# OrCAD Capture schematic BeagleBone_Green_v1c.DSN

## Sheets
1 P01_Title Page: title: BeagleBone Green Cover Page; rev: v1
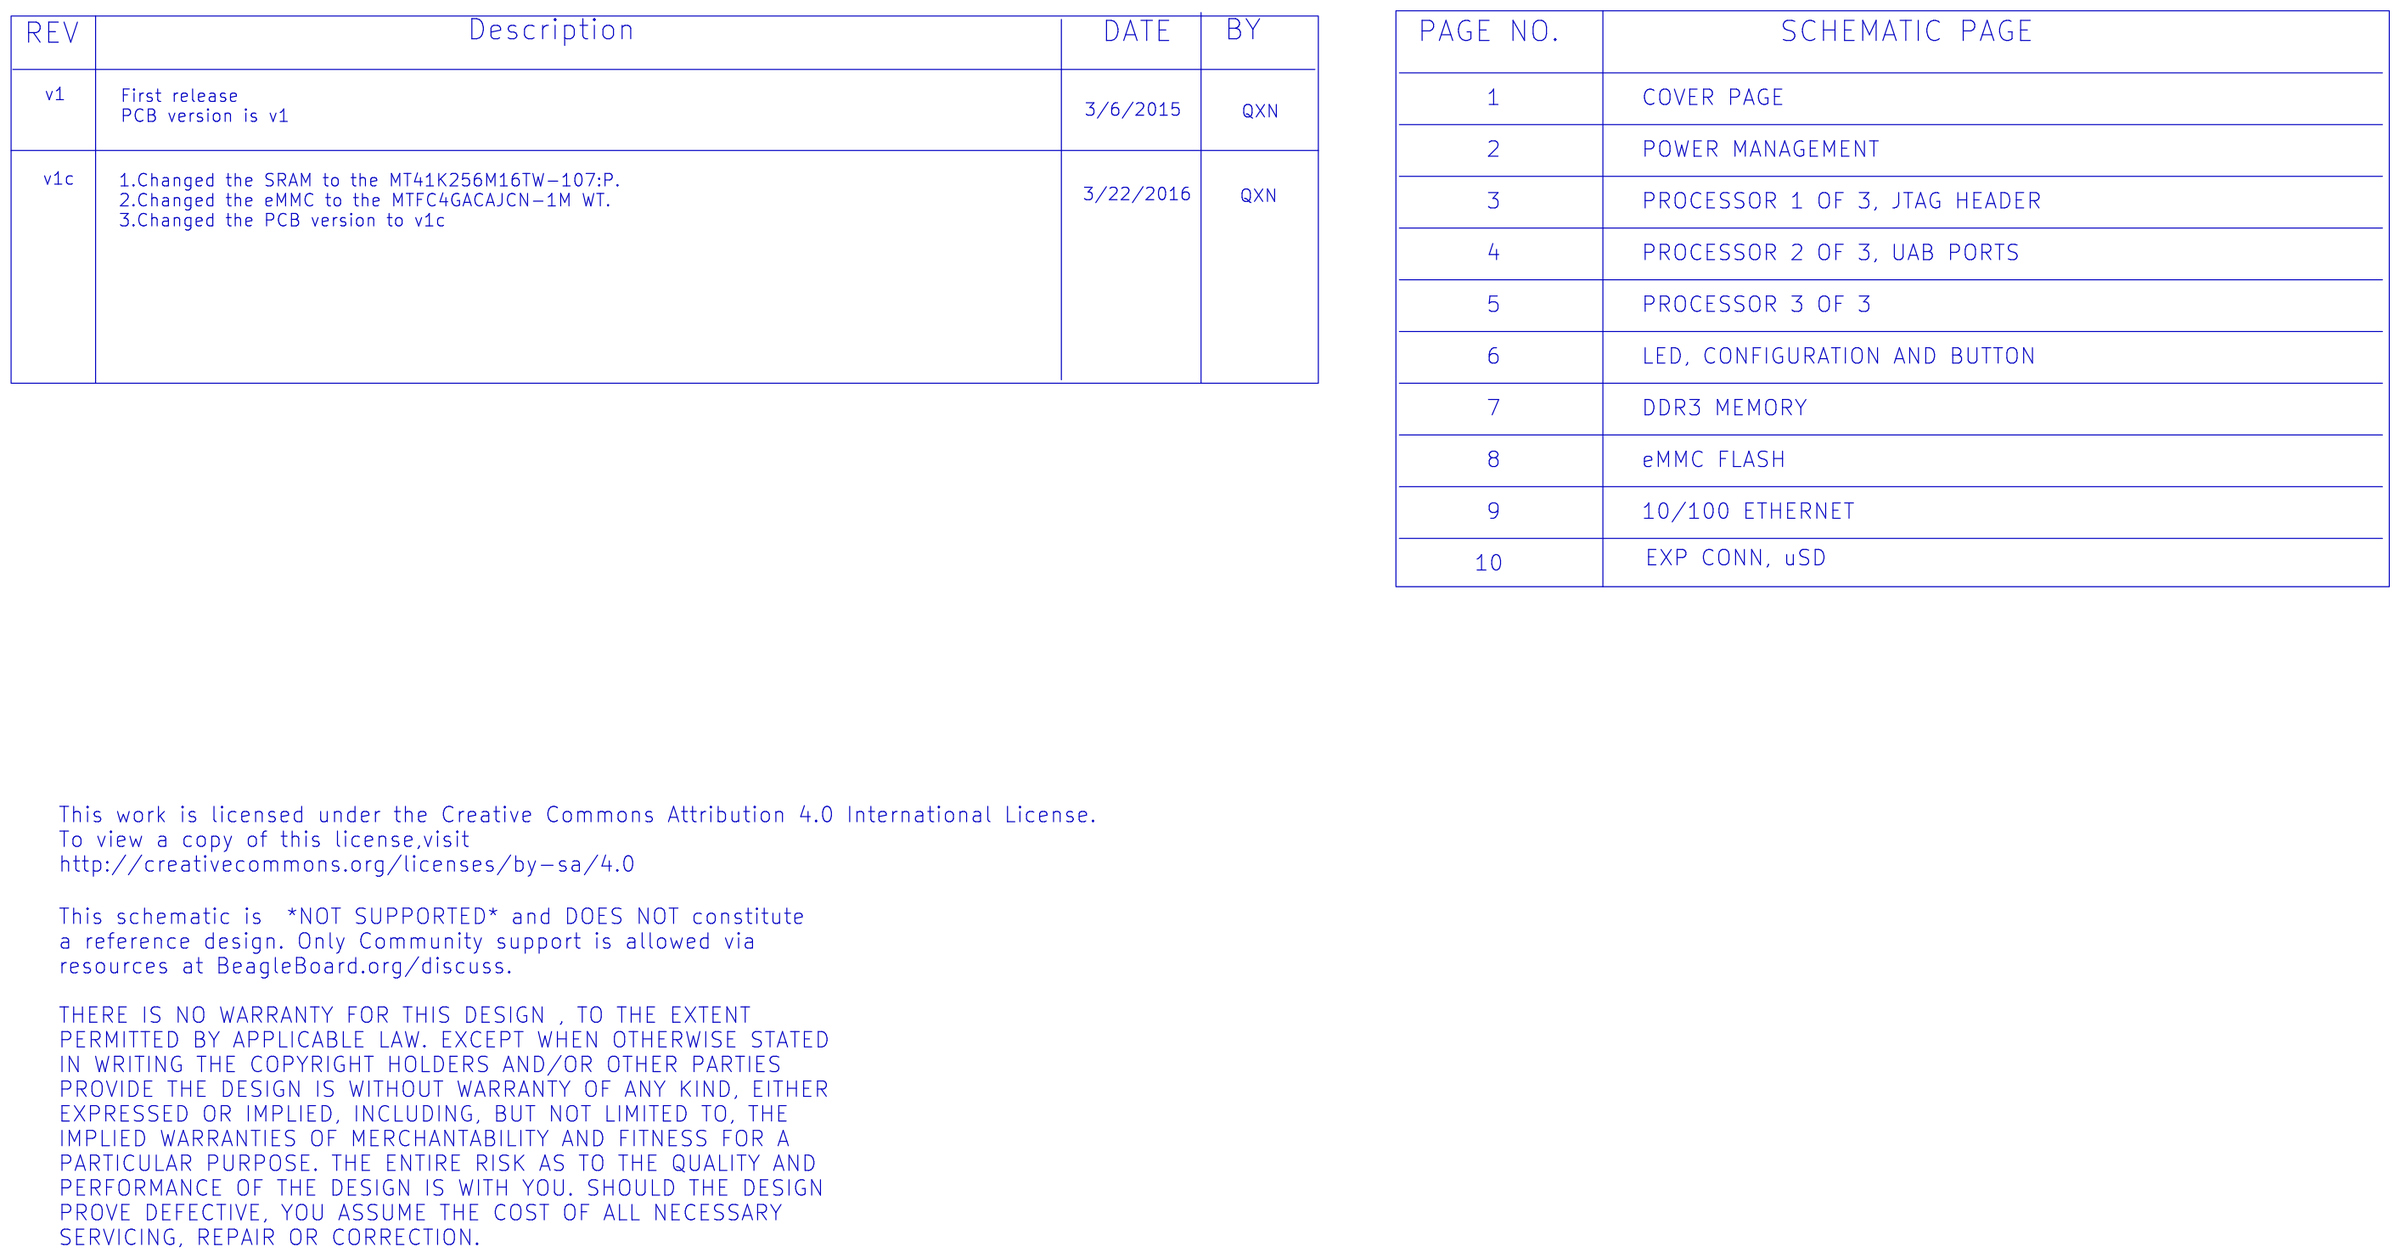
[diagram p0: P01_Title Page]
2 P02_Power Management: size B; title: BeagleBone Green Power Management
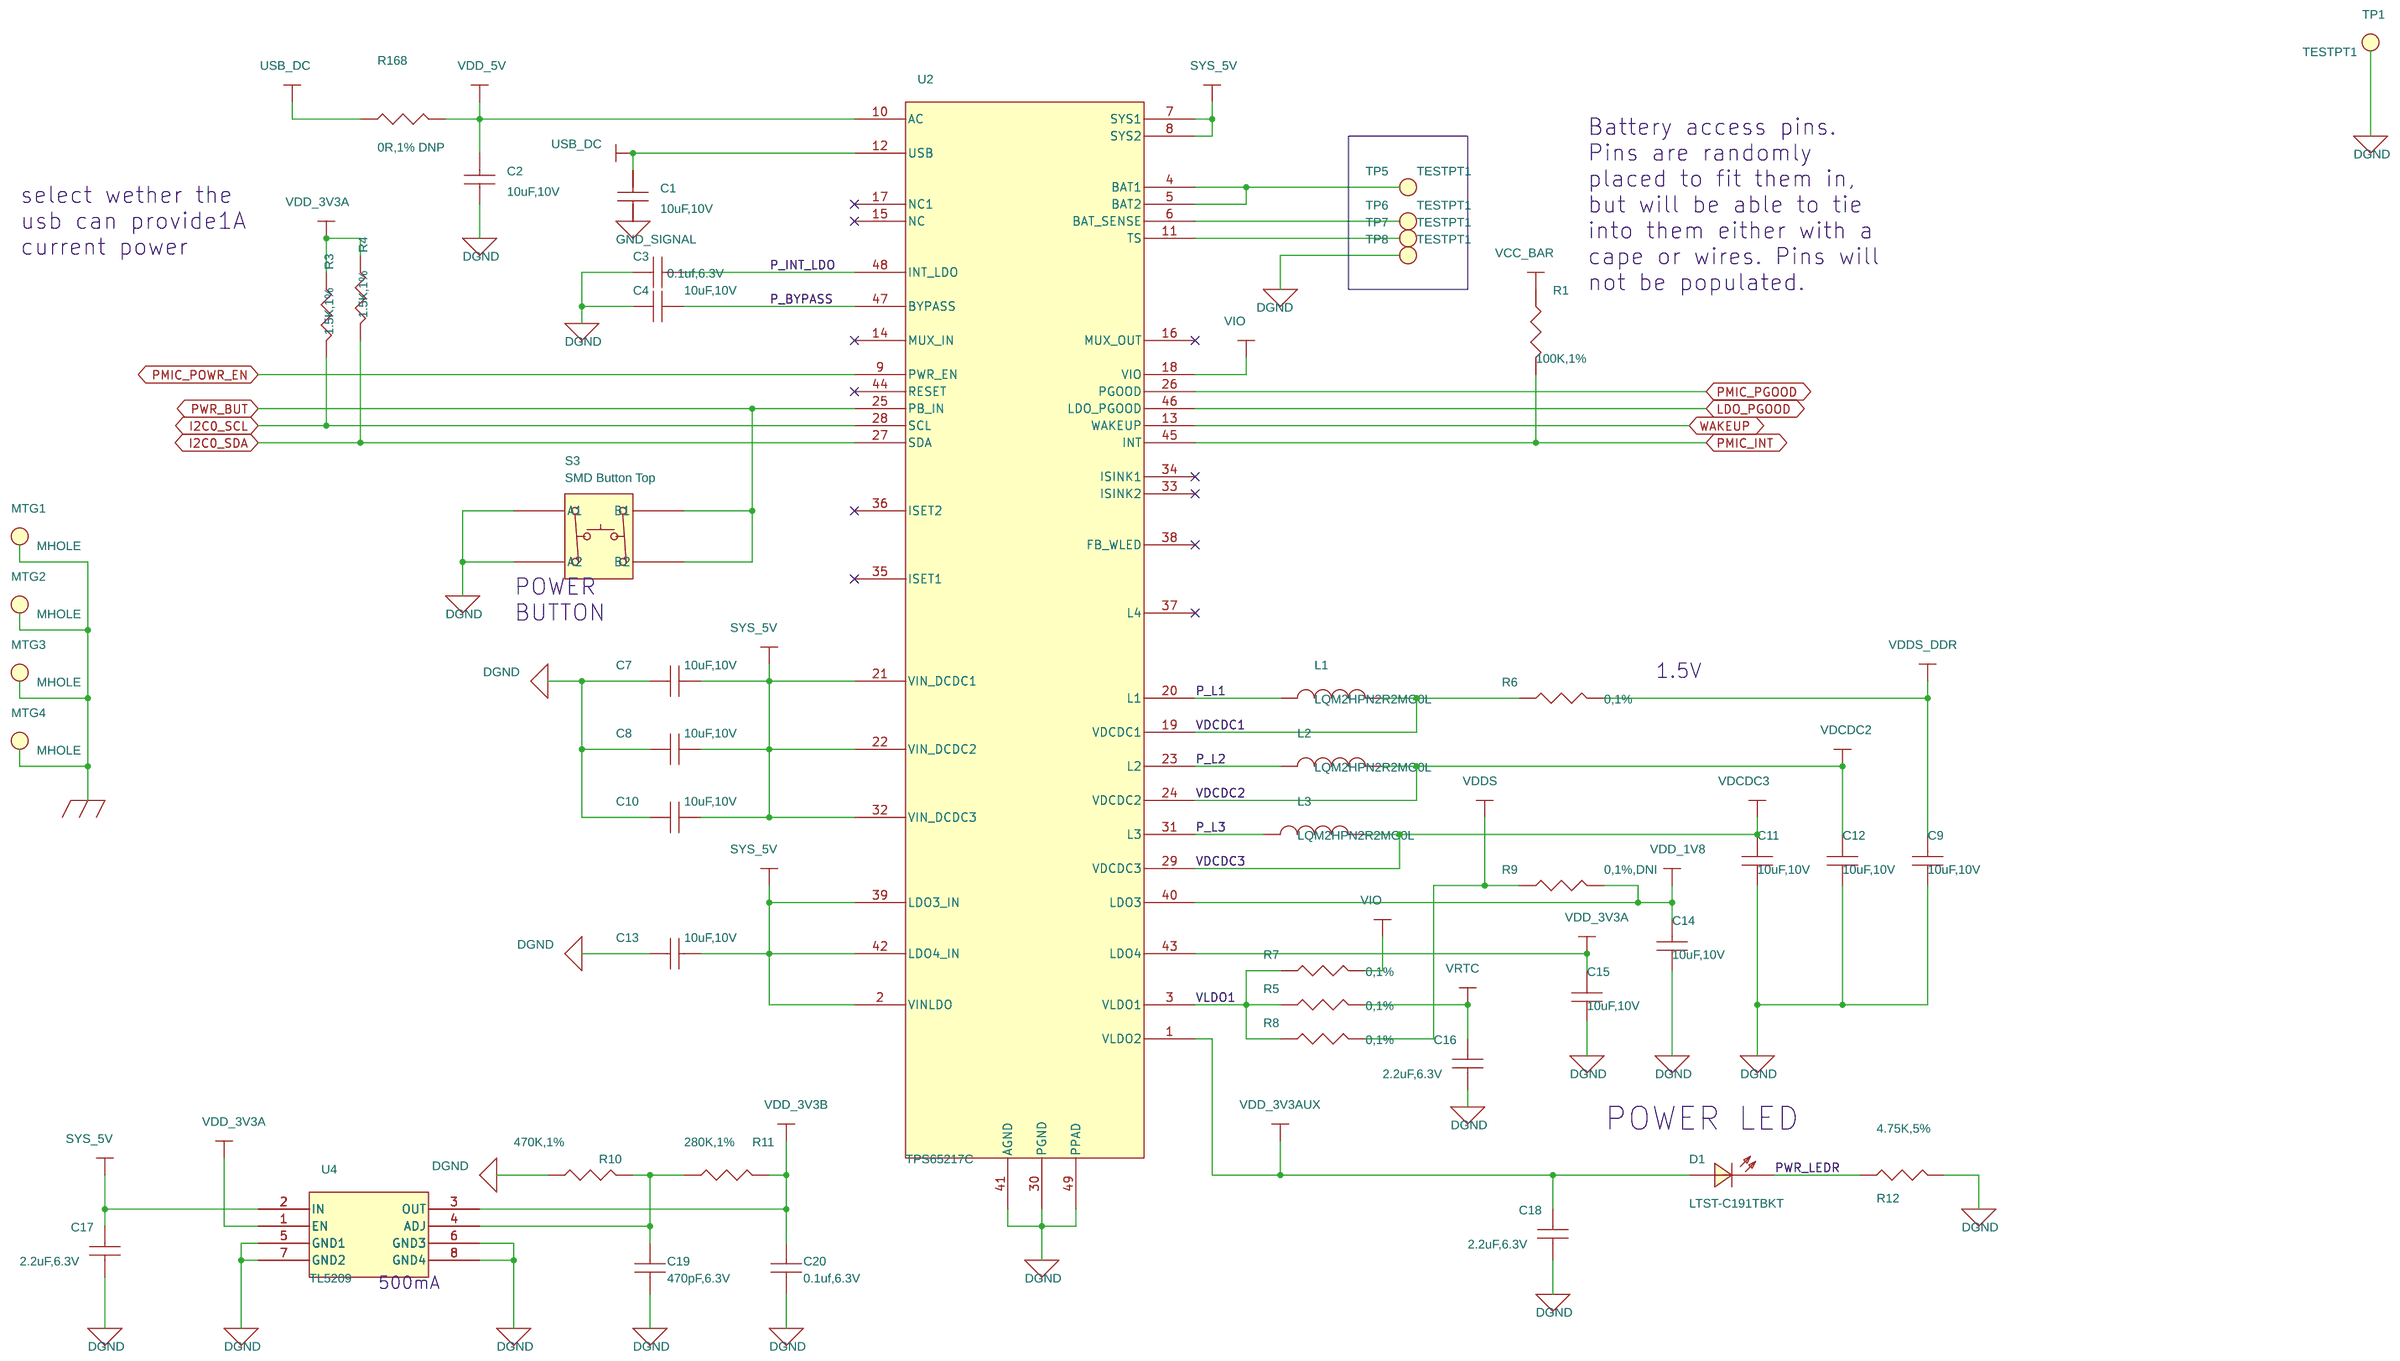
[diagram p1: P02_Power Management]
3 P06_LED, Config: size B; title: BeagleBone Green LED, Configuration, and Reset
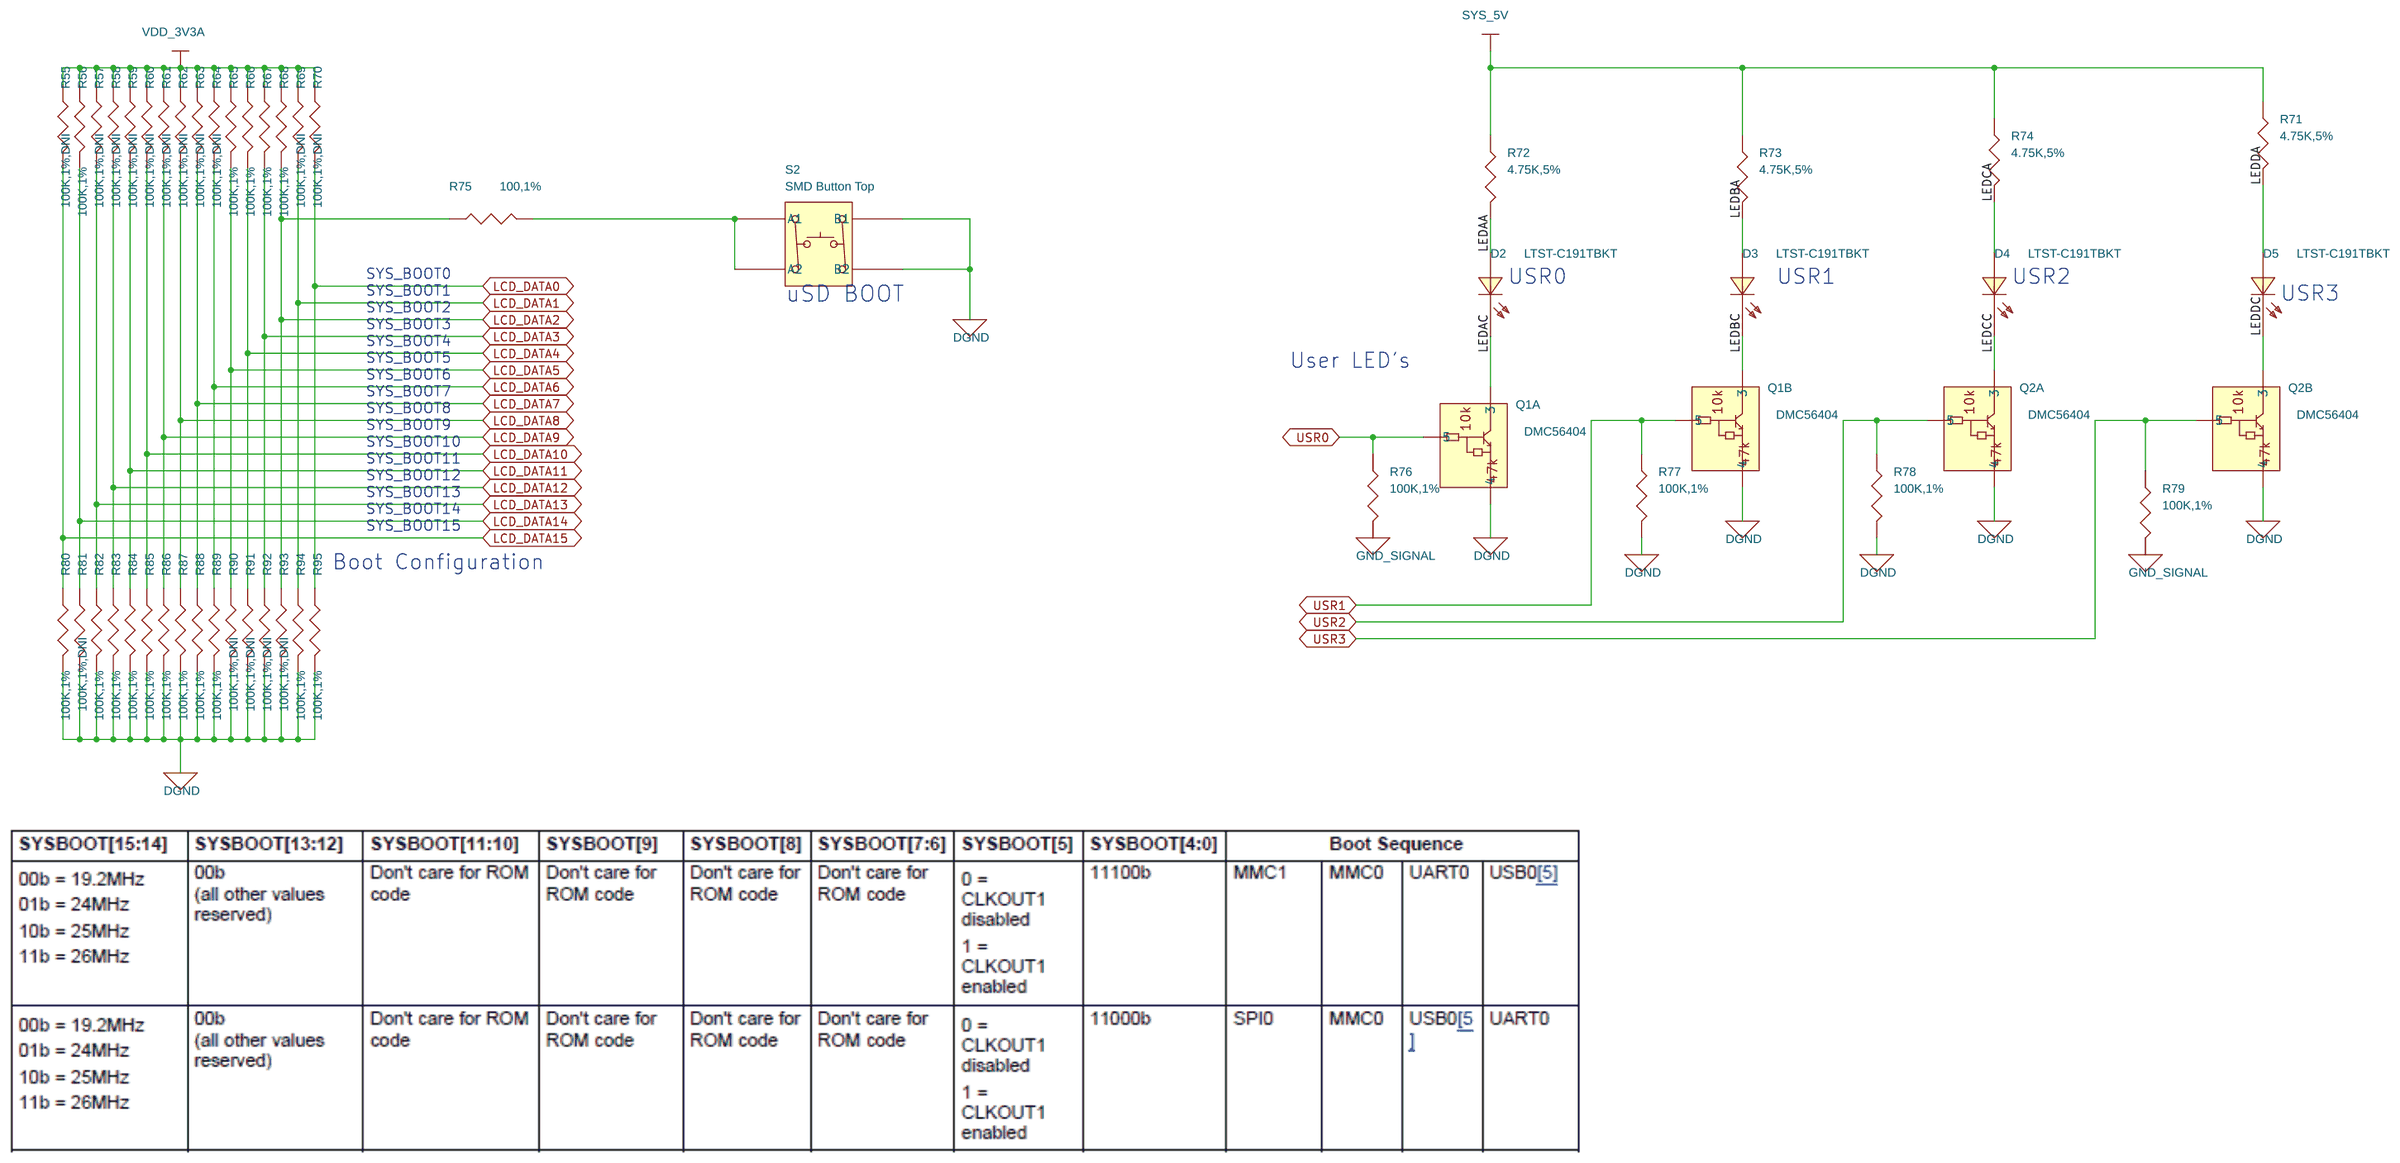
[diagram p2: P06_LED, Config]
4 P07_DDR3 Memory: size B; title: BeagleBone Green DDR3 Memory
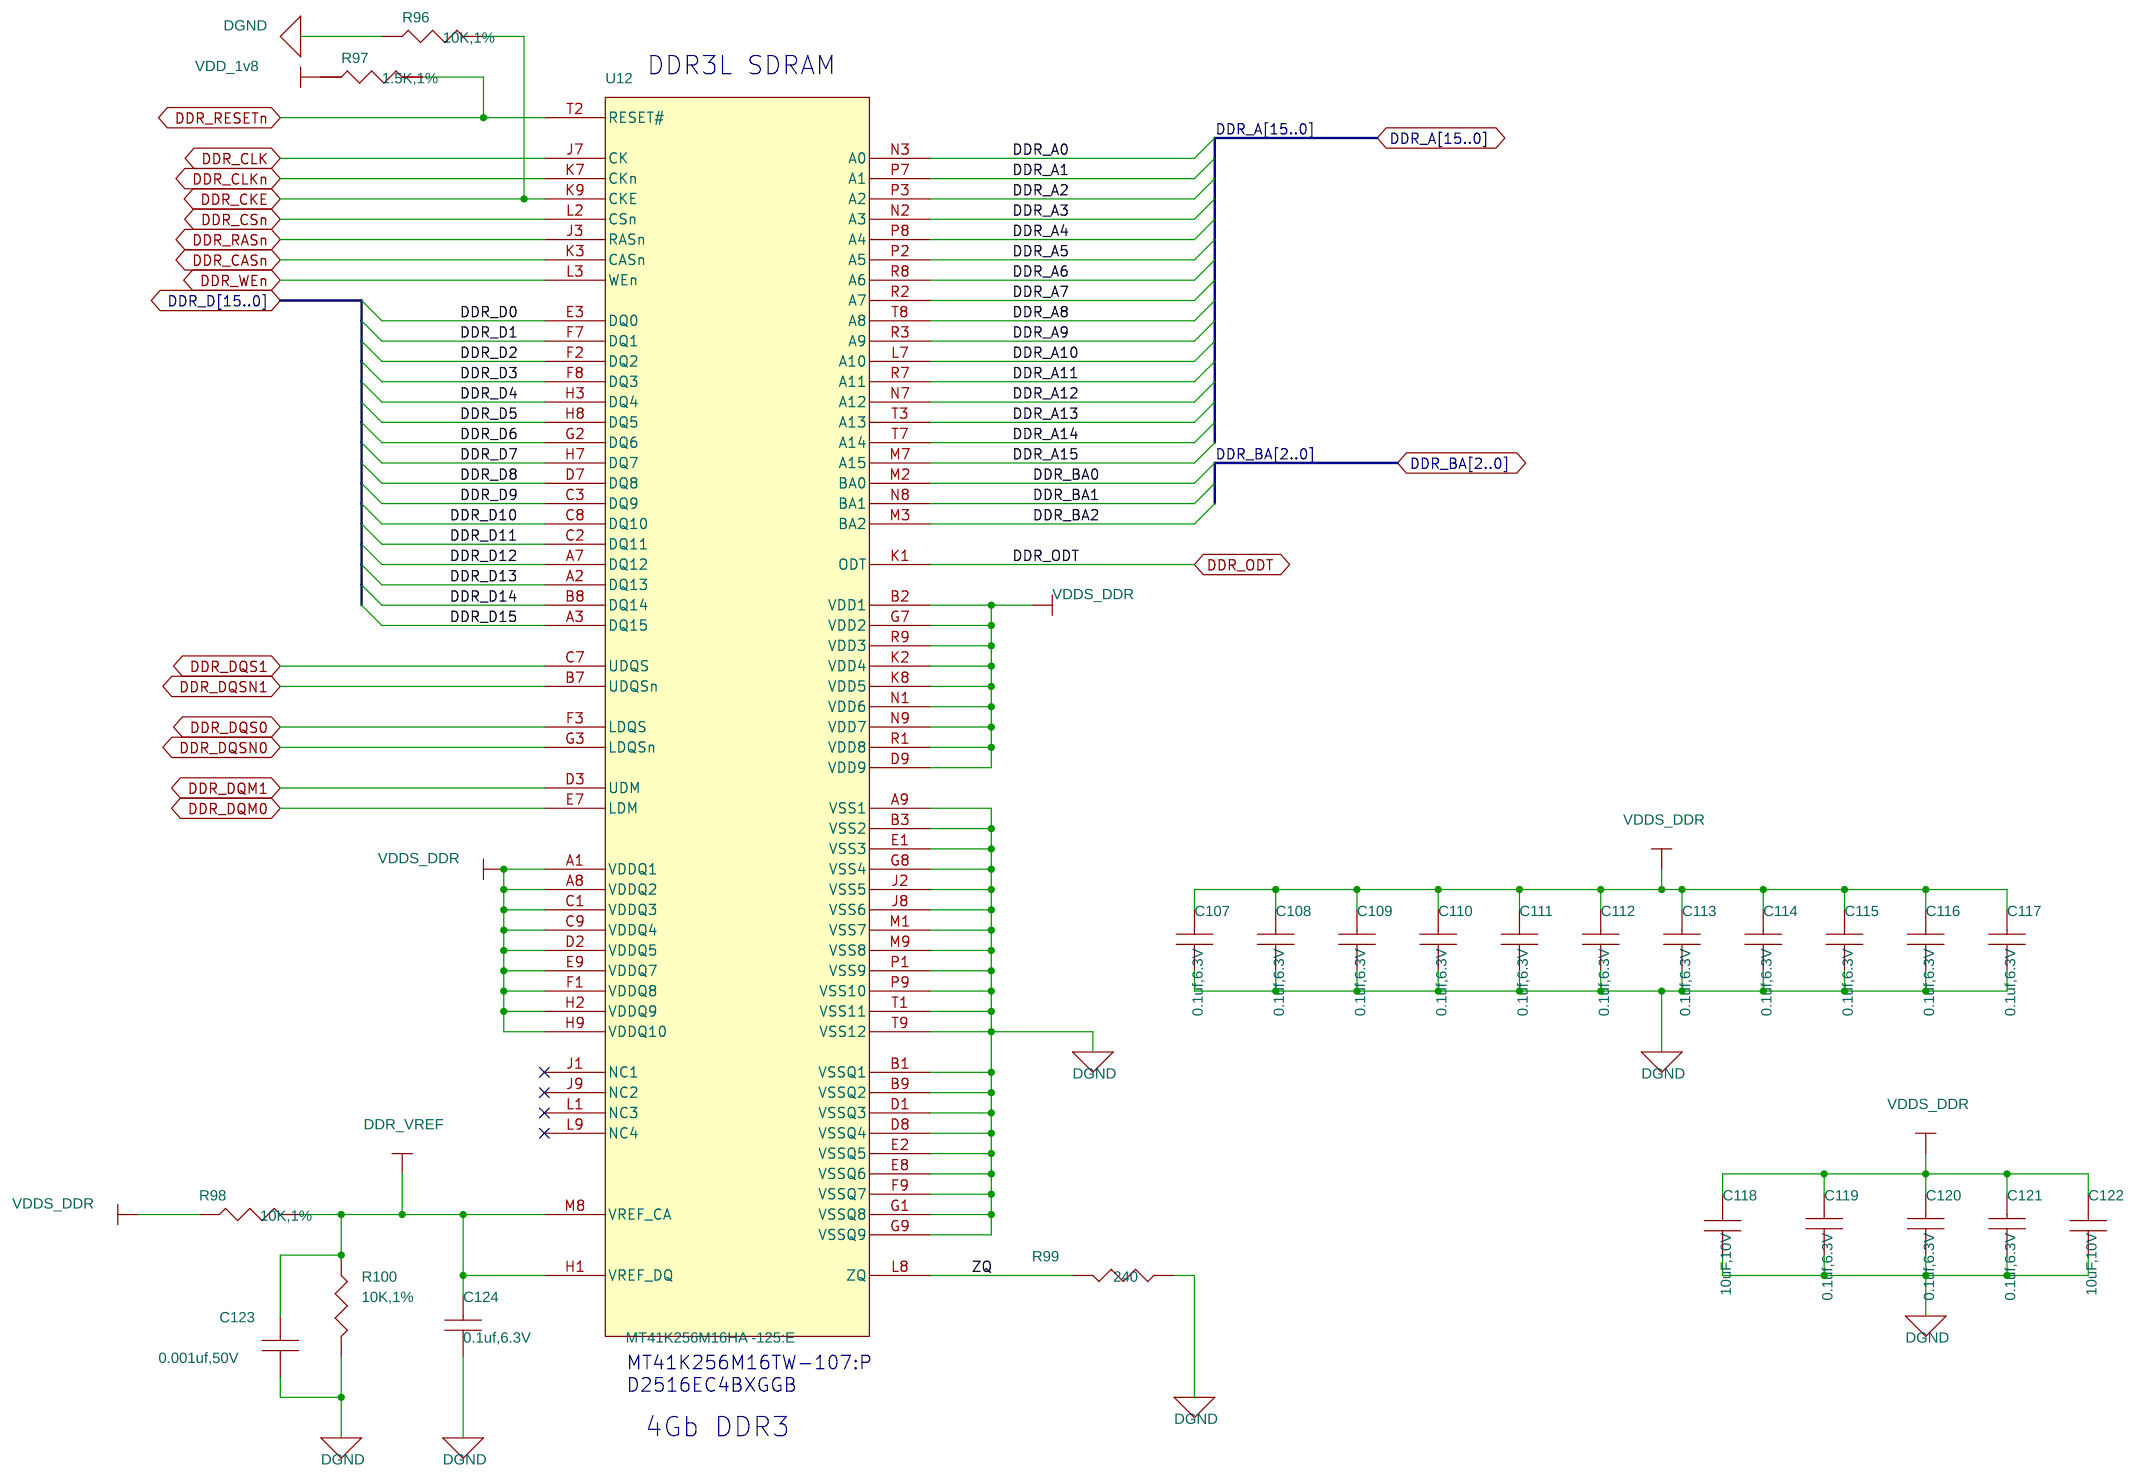
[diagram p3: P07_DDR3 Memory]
5 P08_eMMC FLASH: size B; title: BeagleBone Green 4G eMMC
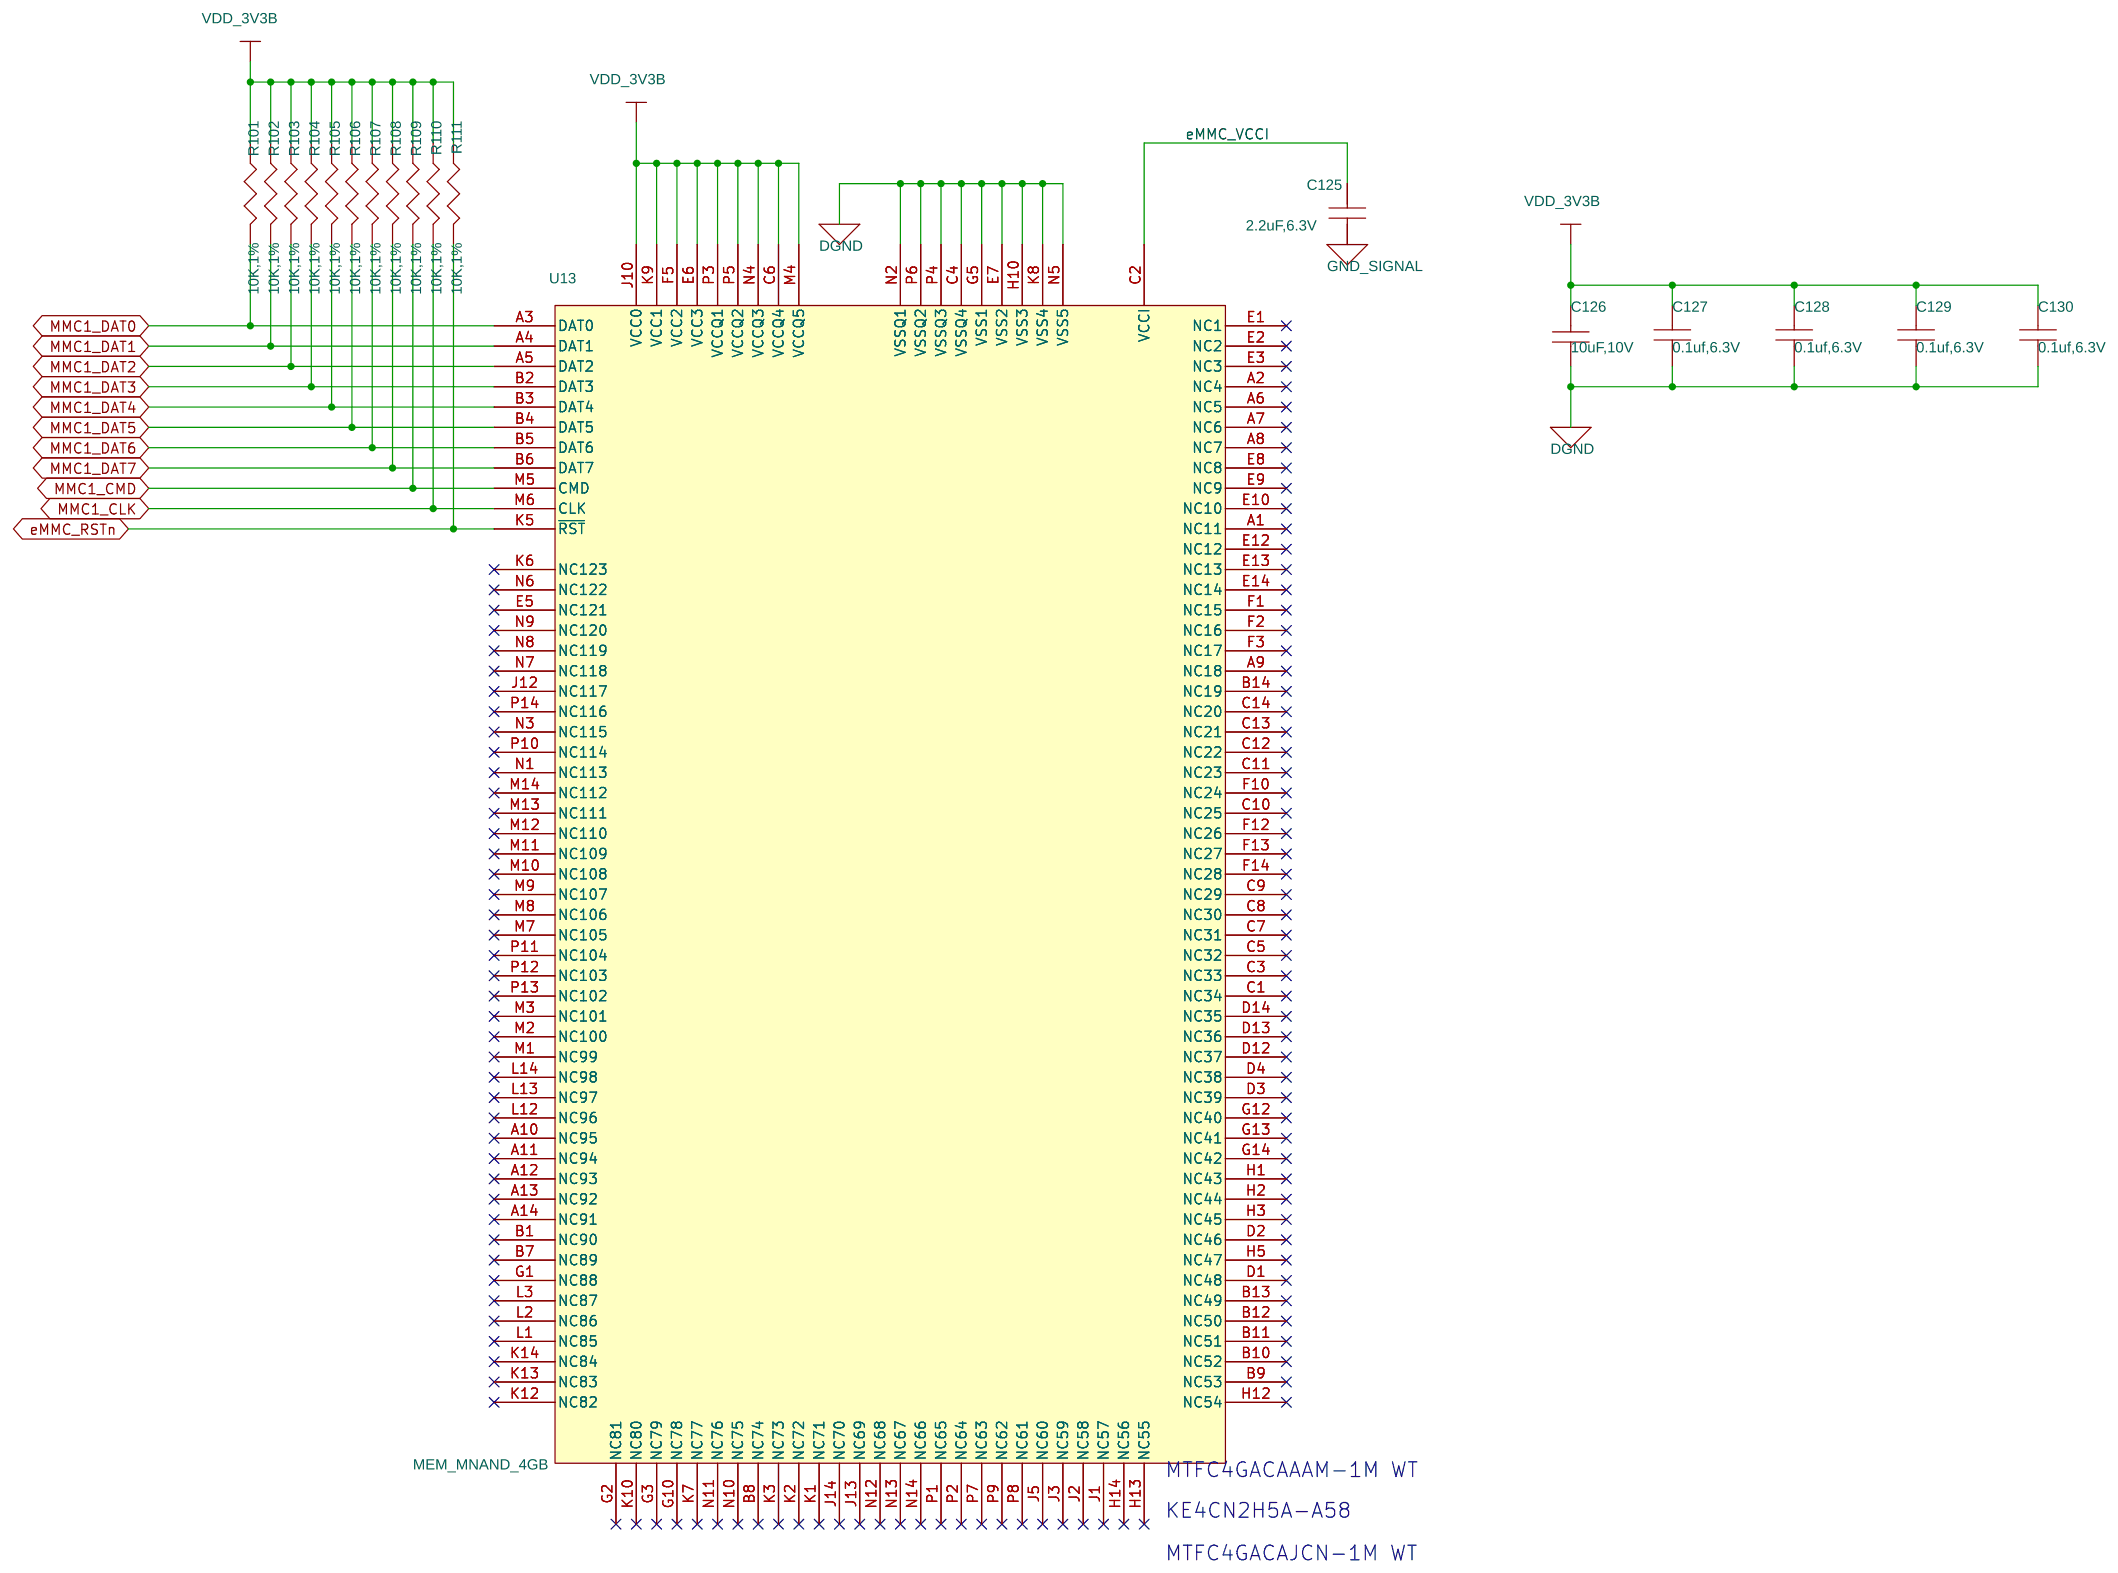
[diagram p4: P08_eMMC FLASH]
6 P10_Exp Conn, uSD: size B; title: BeagleBone Green Expansion Headers, uSD.and EEPROM
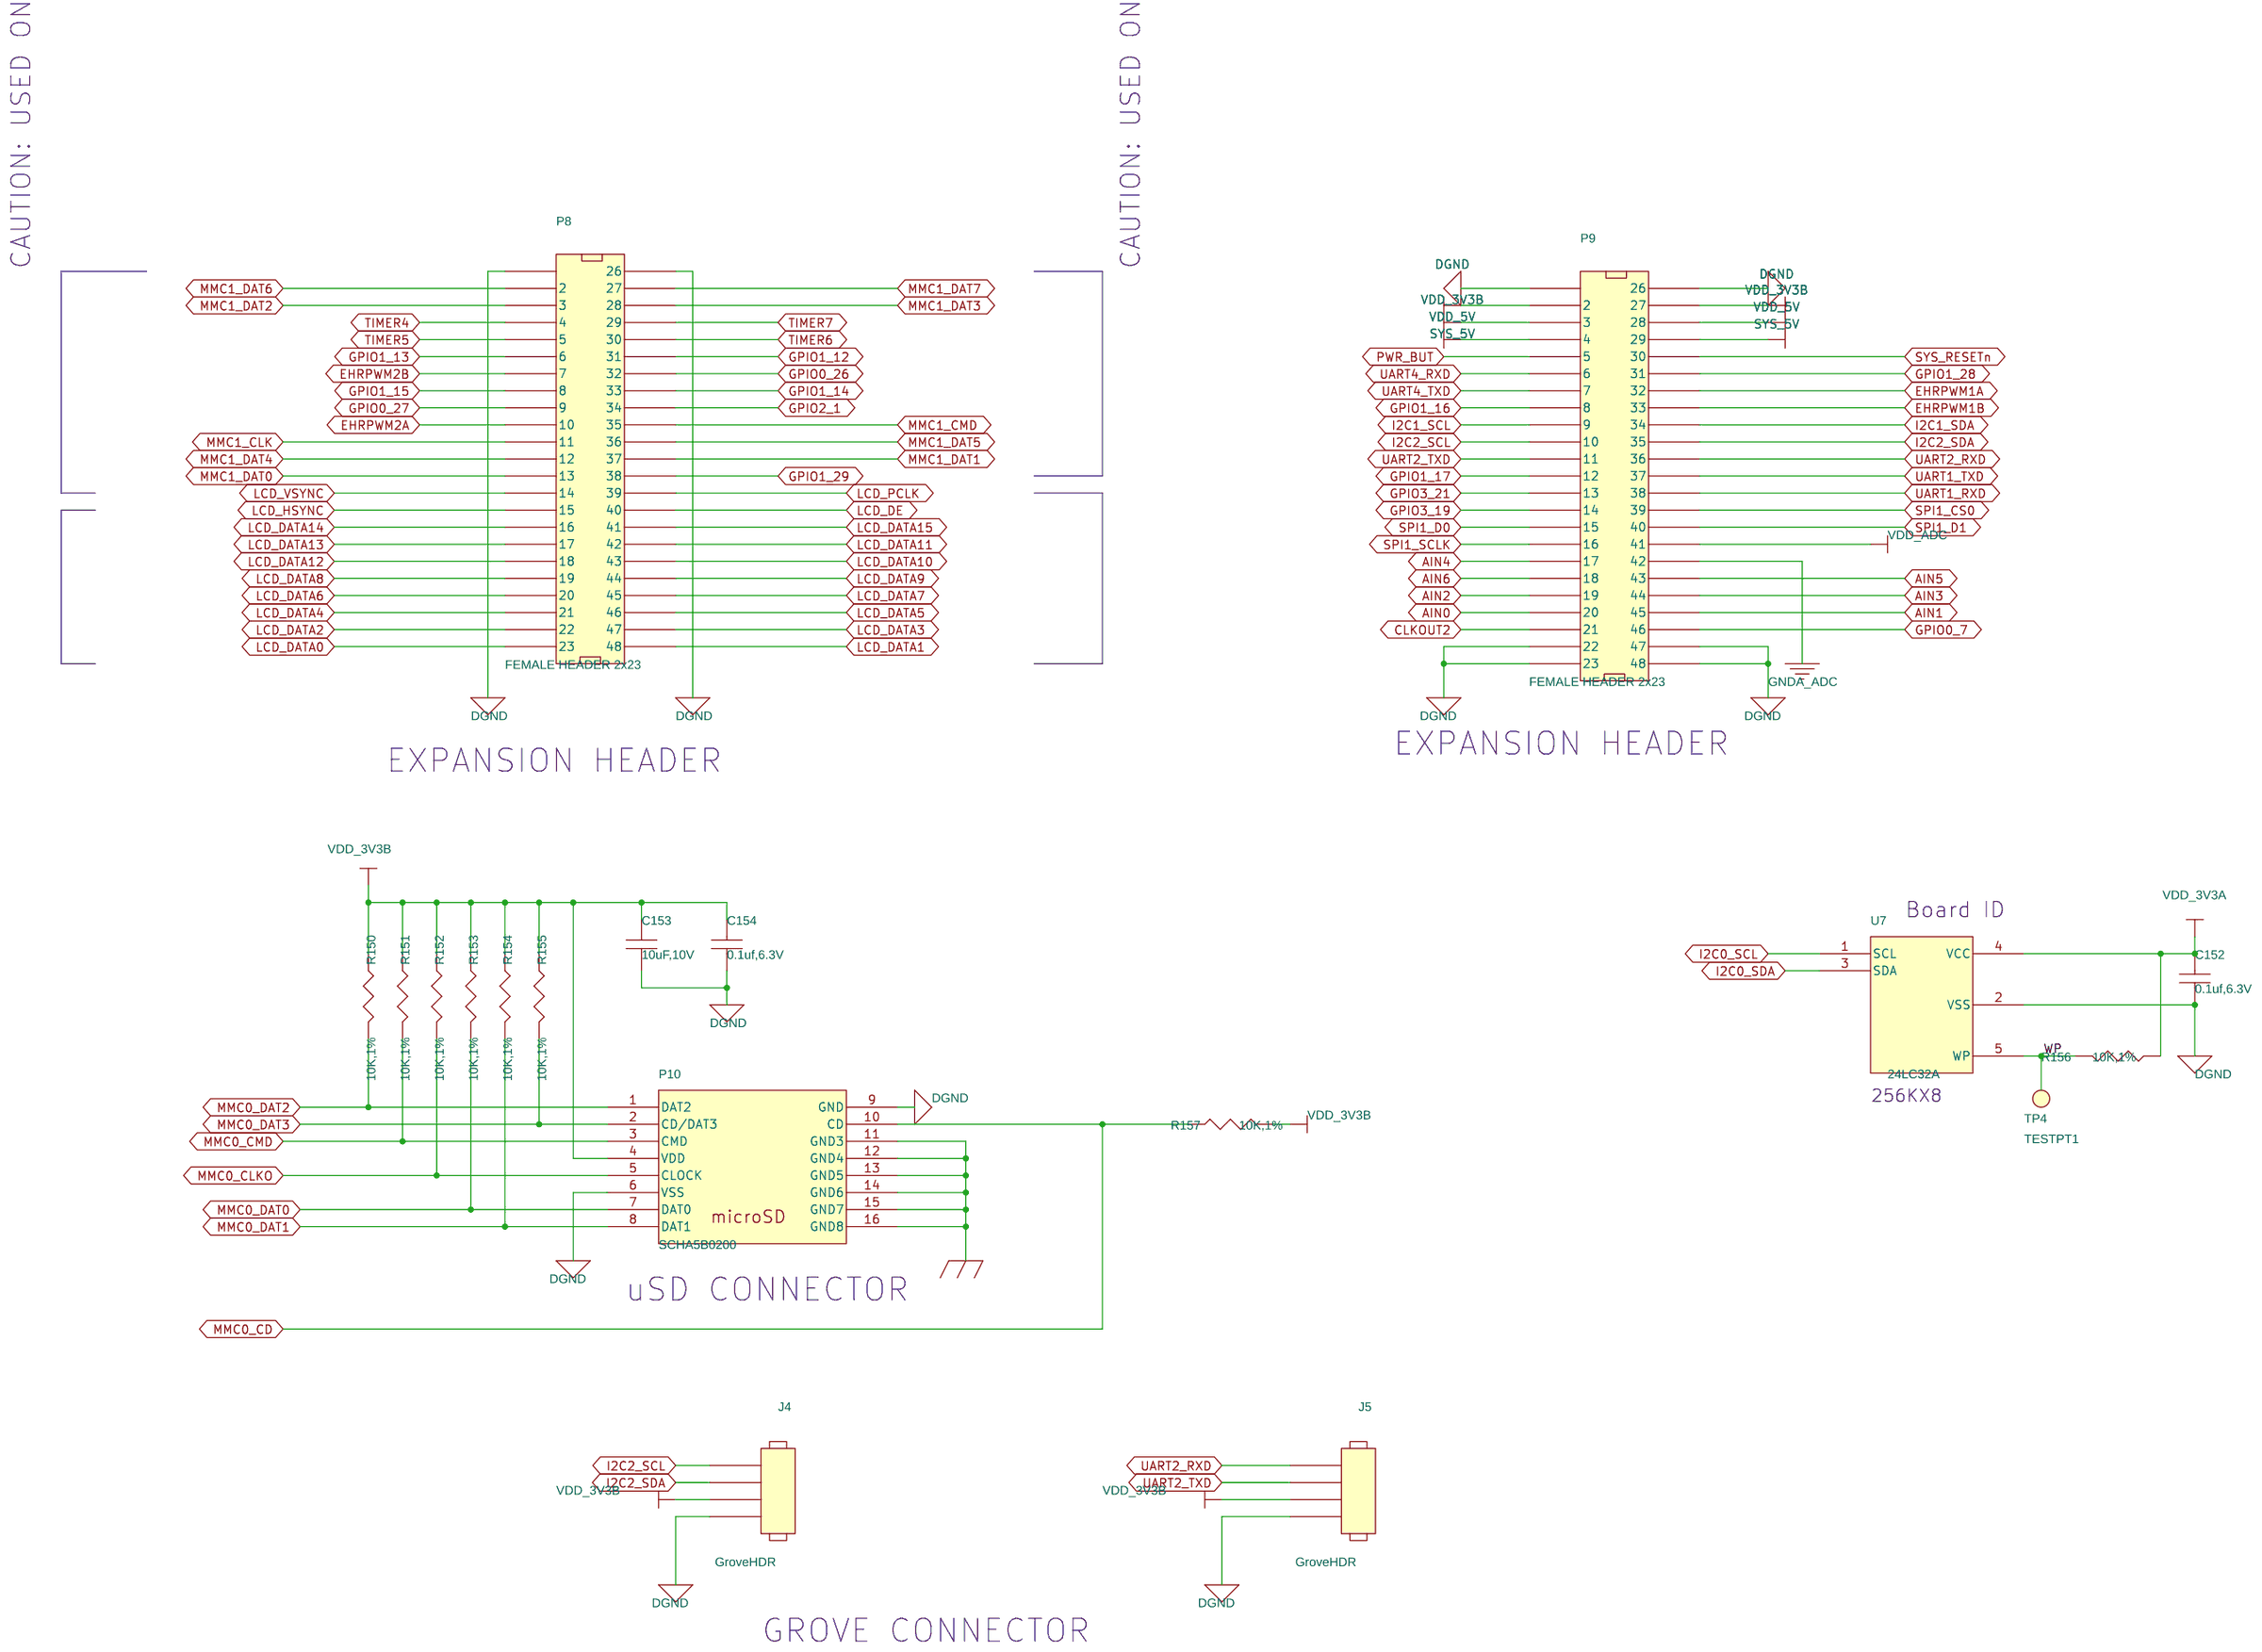
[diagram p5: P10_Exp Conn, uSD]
7 P05_AM335x 3/3: size C; title: BeagleBone Green Processr 3 of 3
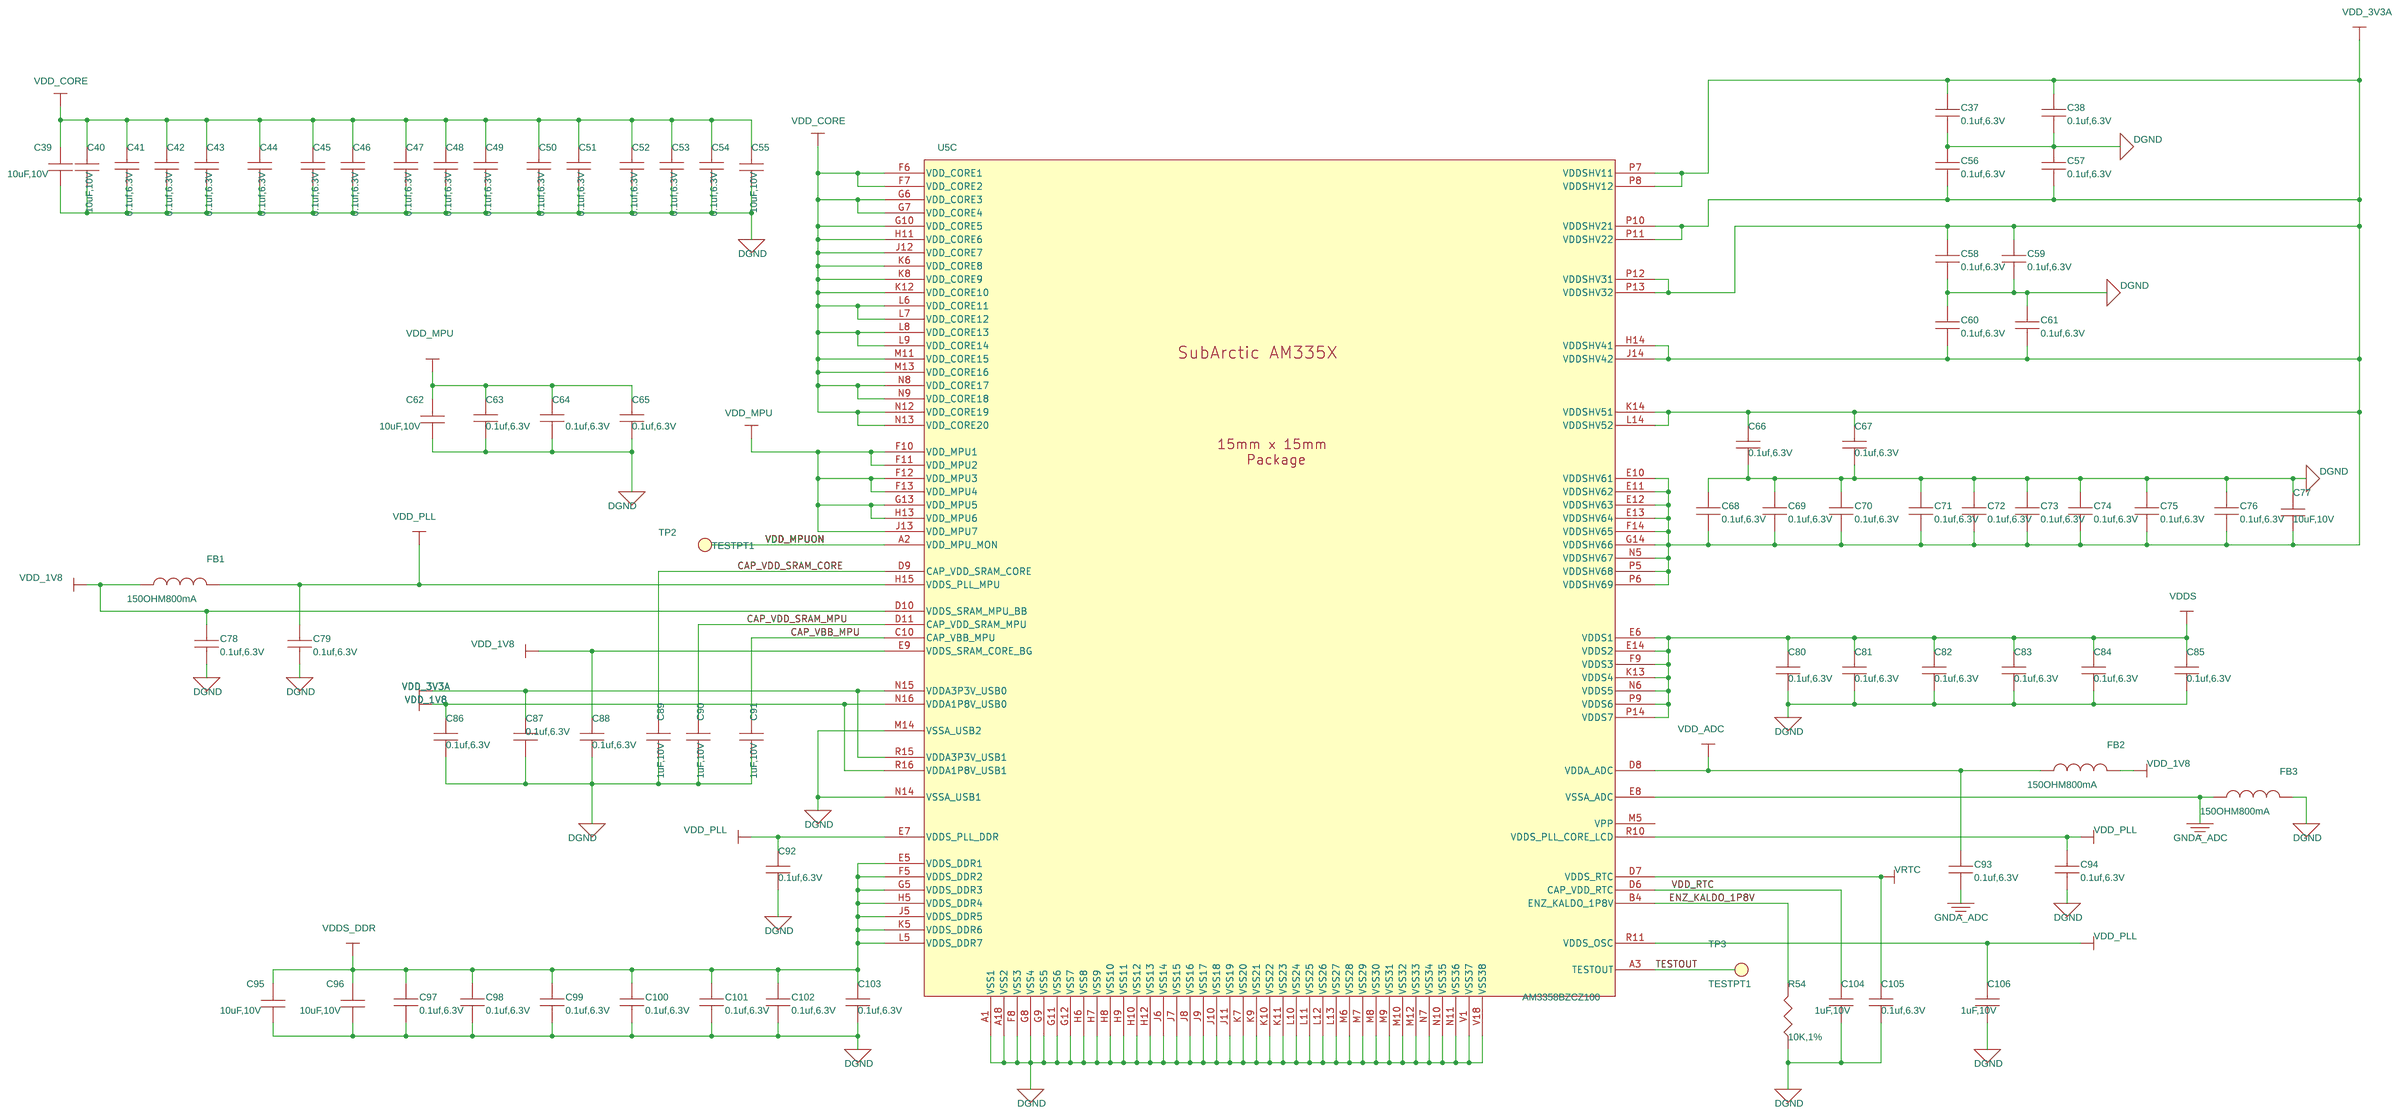
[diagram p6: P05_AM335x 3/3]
8 P09_10/100 Ethernet: size B; title: BeagleBone Green Ethernet
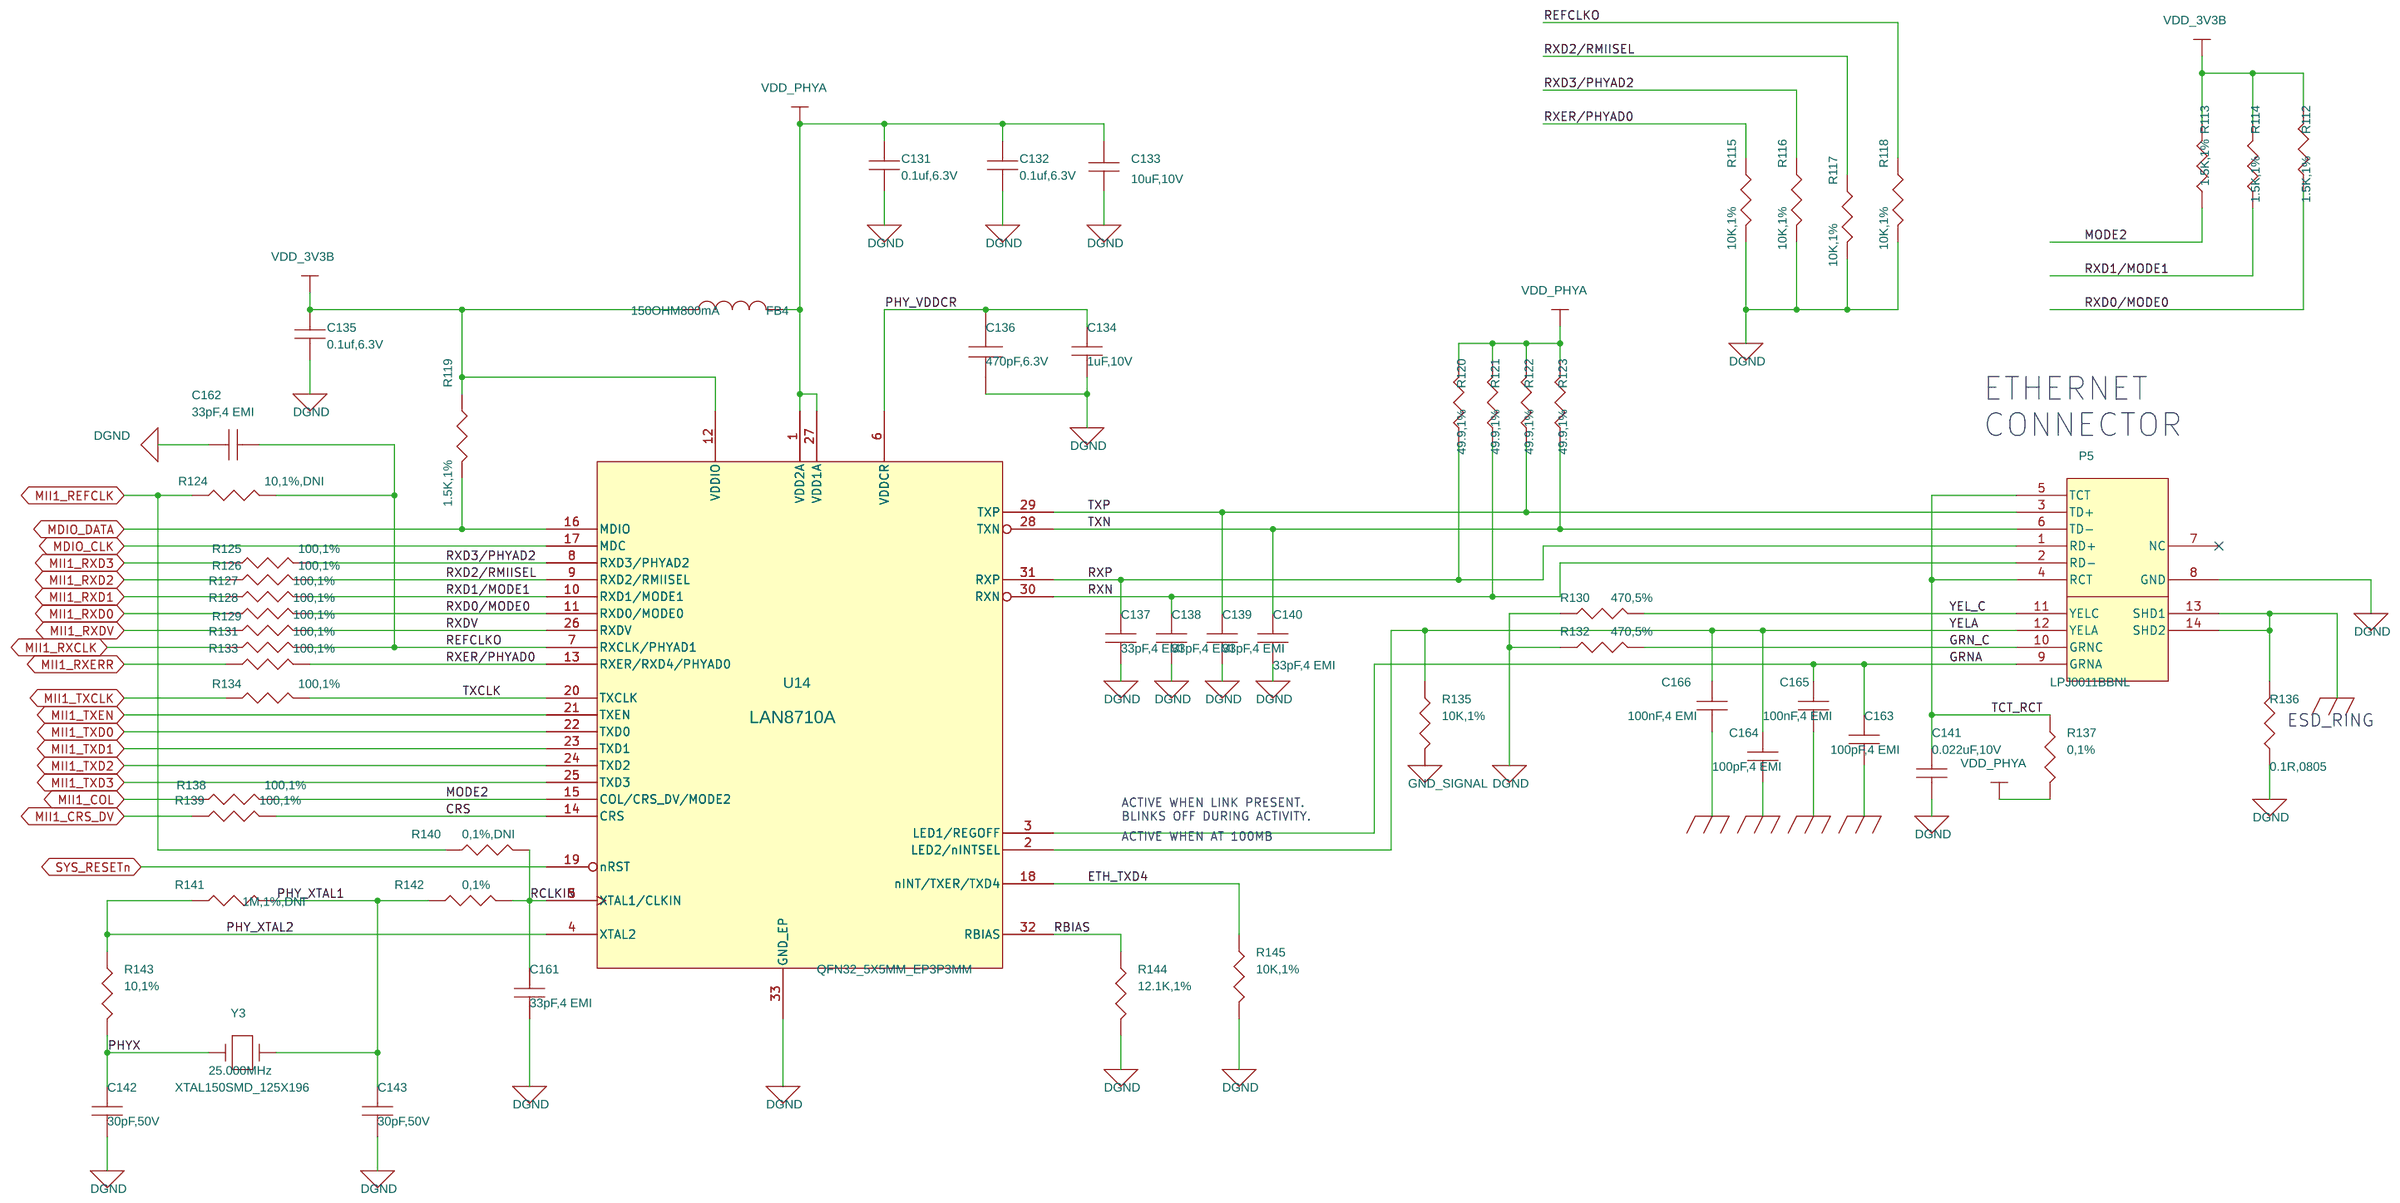
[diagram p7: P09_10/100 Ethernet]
9 P04_AM335x 2/3, USB: size C; title: BeagleBone Green Processor 2 of 3, USB,  and Serial
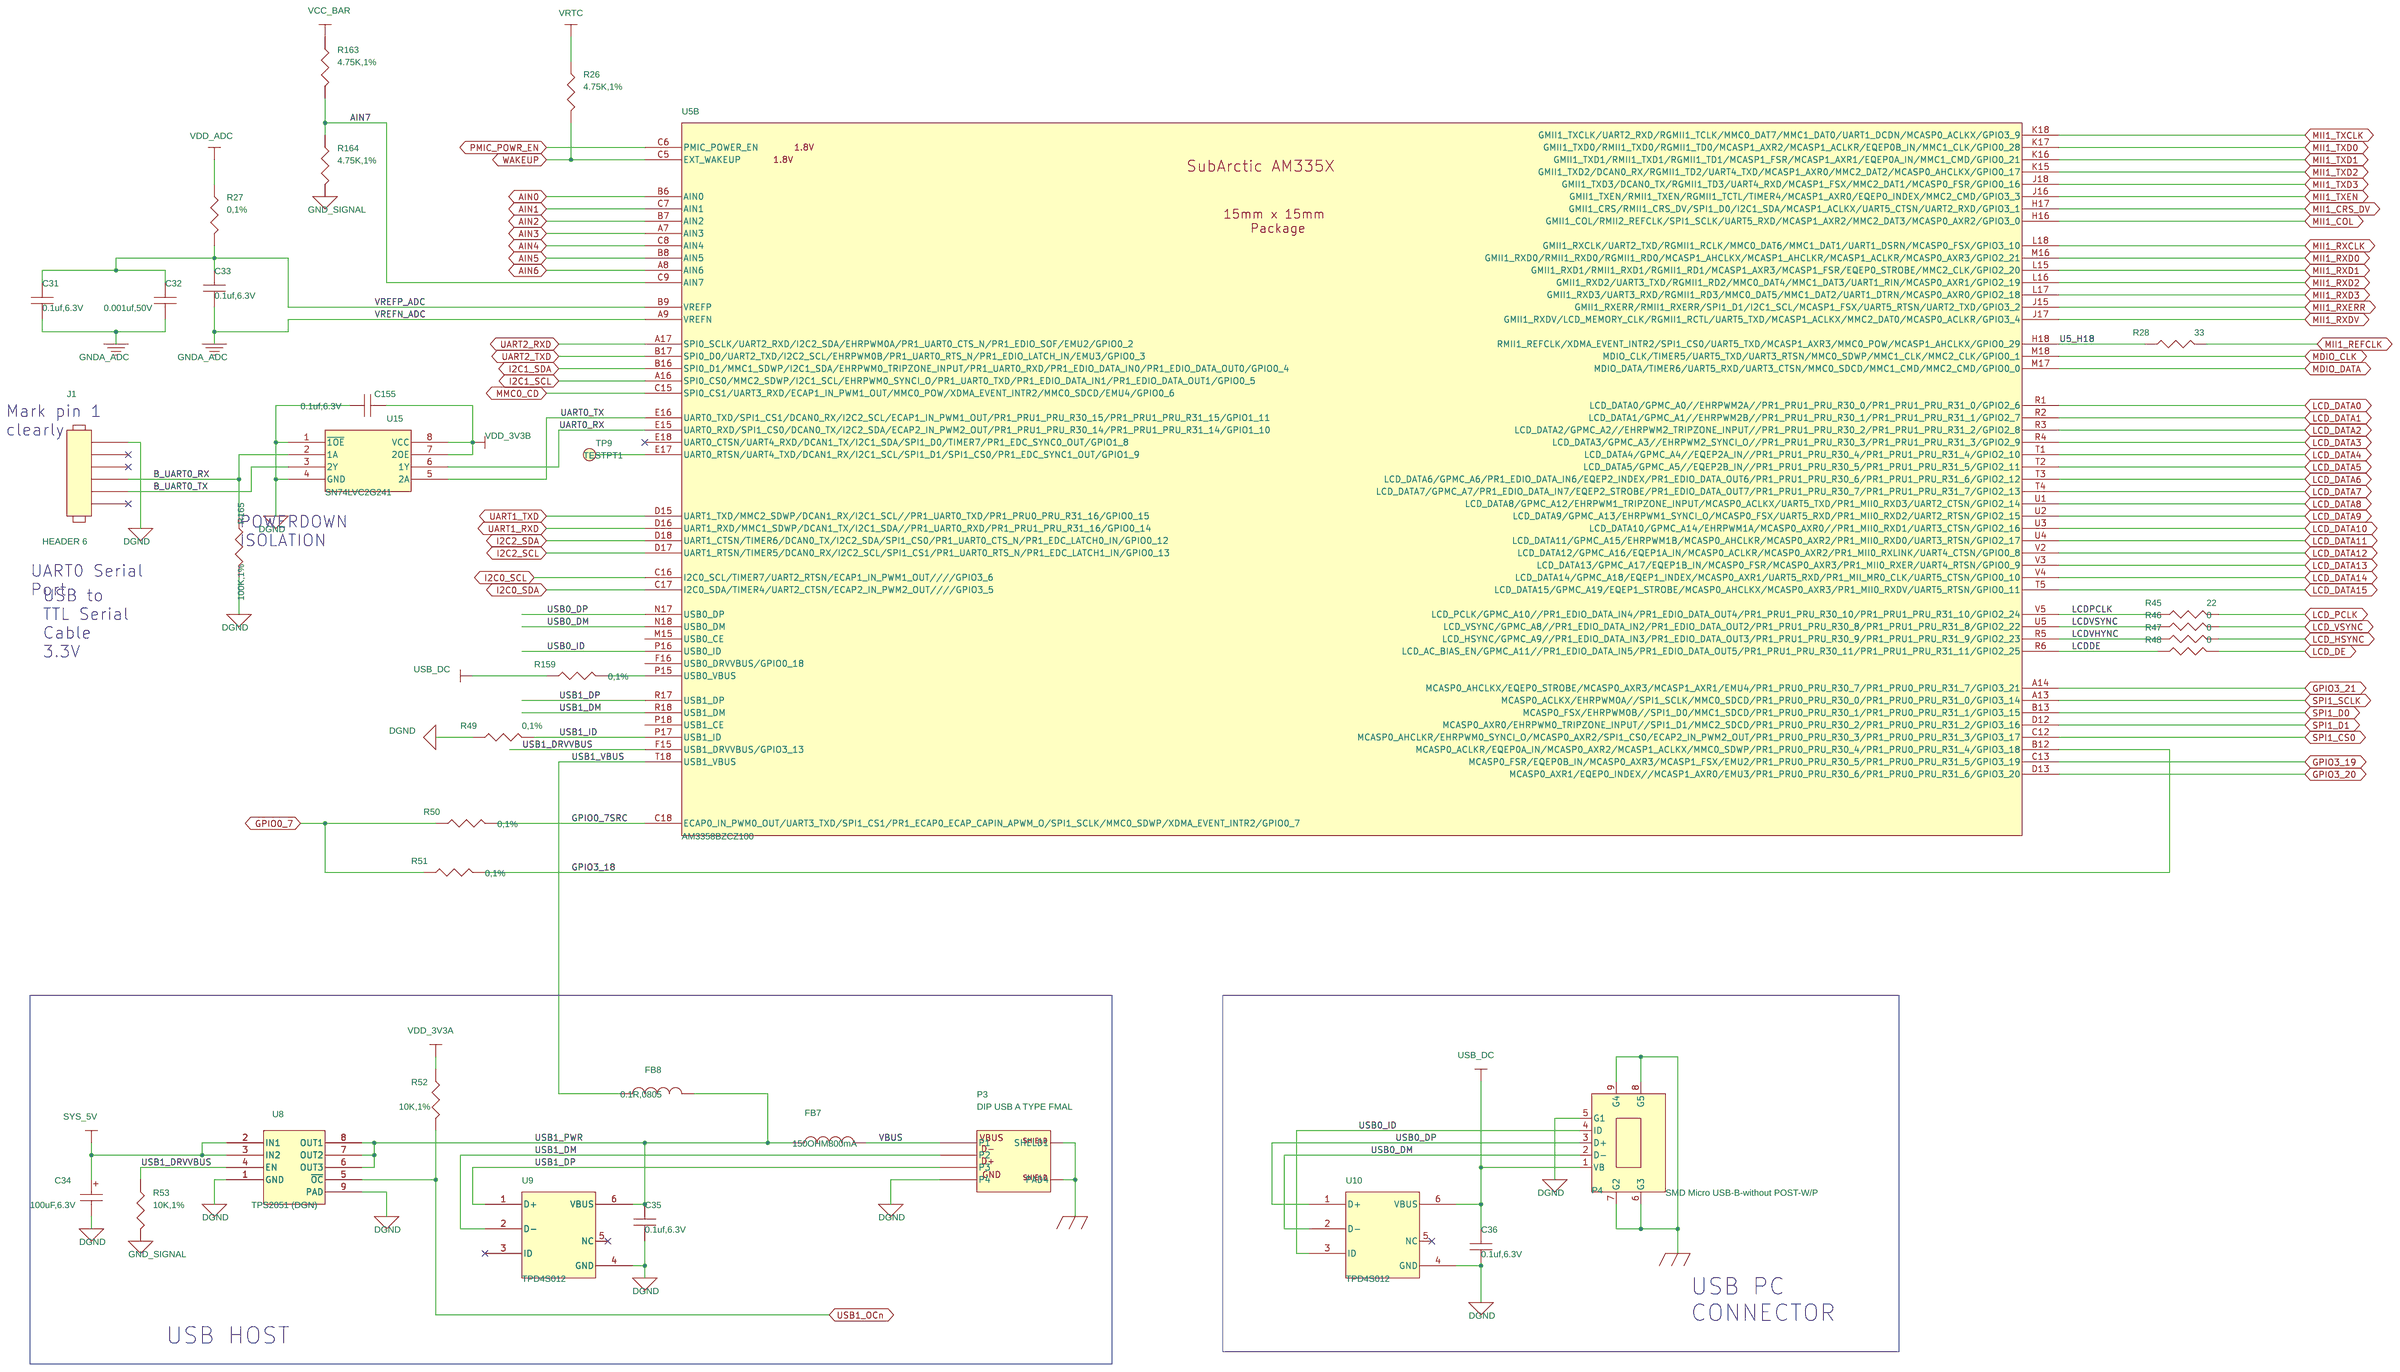
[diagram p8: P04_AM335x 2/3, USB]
10 P03_AM335x 1/3, JTAG: size C; title: BeagleBone Green Processor 1 of 3 and JTAG
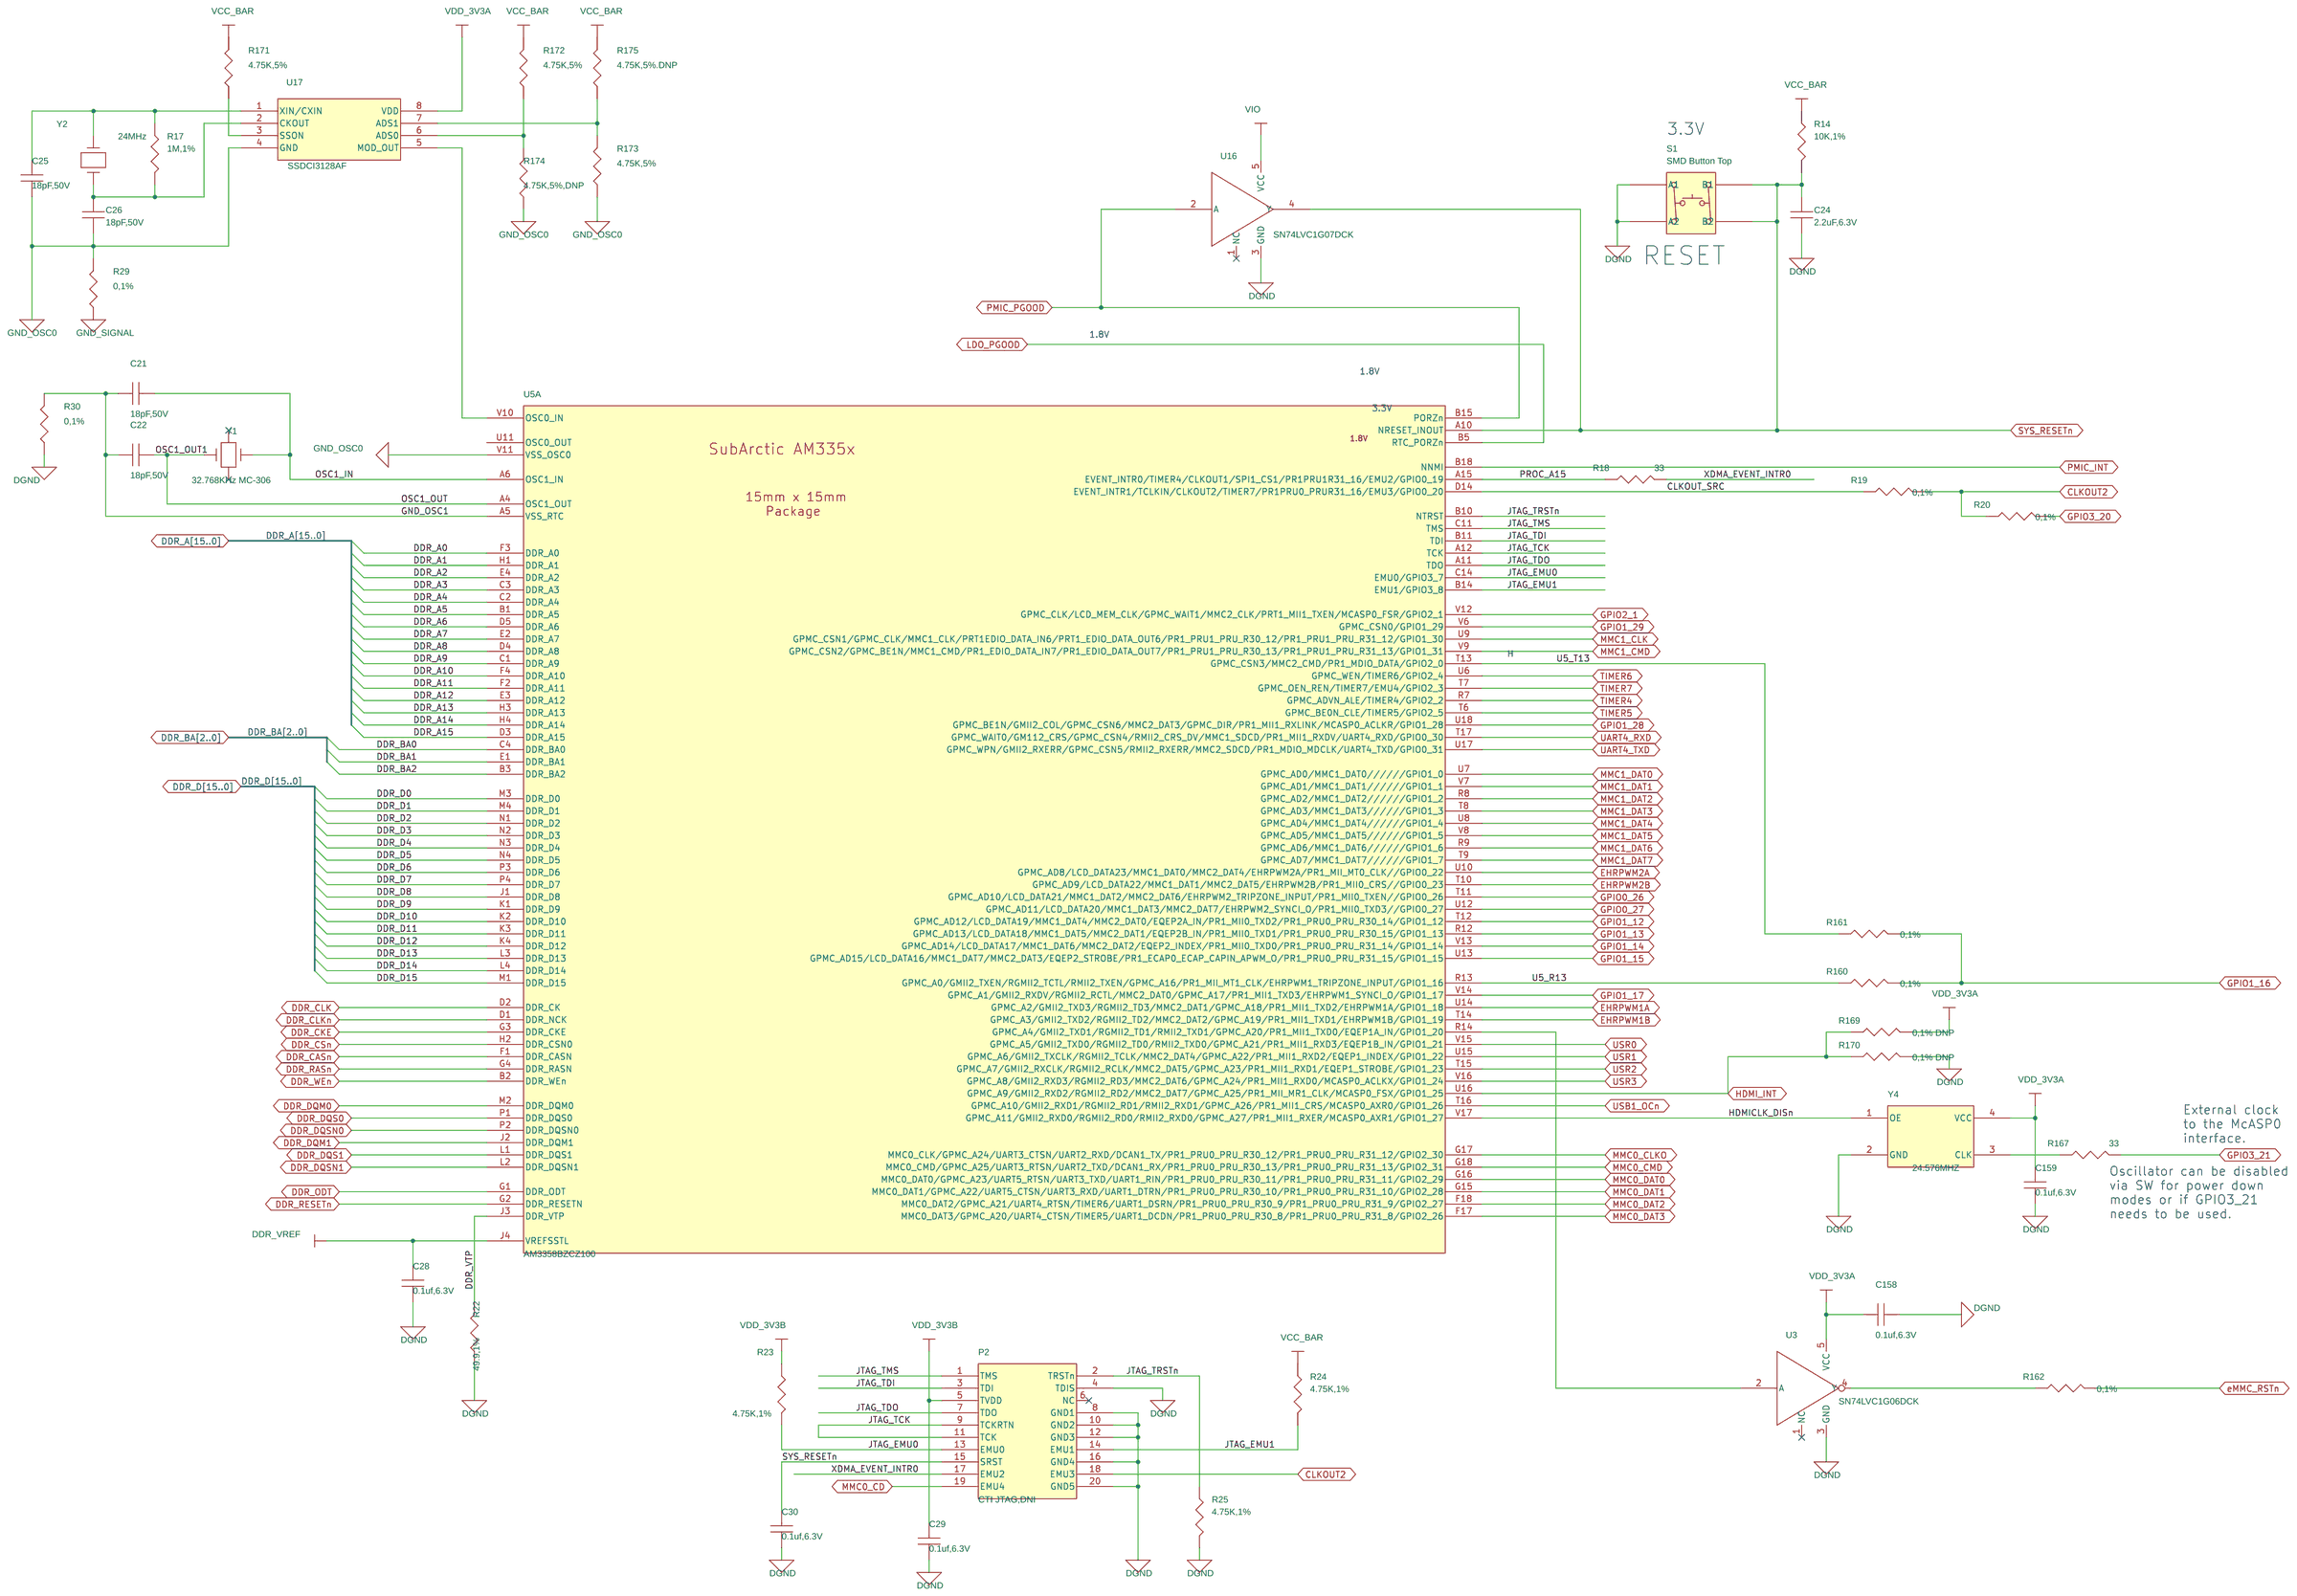
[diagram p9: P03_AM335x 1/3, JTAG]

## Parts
sheet P02_Power Management
C1  10uF,10V  [805]
C2  10uF,10V  [805]
C3  0.1uf,6.3V  [402]
C4  10uF,10V  [805]
C7  10uF,10V  [805]
C8  10uF,10V  [805]
C9  10uF,10V  [805]
C10  10uF,10V  [805]
C11  10uF,10V  [805]
C12  10uF,10V  [805]
C13  10uF,10V  [805]
C14  10uF,10V  [805]
C15  10uF,10V  [805]
C16  2.2uF,6.3V  [402]
C17  2.2uF,6.3V  [402]
C18  2.2uF,6.3V  [402]
C19  470pF,6.3V  [402]
C20  0.1uf,6.3V  [402]
D1  LTST-C191TBKT  [LED_0603]
L1  LQM2HPN2R2MG0L  [2520]
L2  LQM2HPN2R2MG0L  [2520]
L3  LQM2HPN2R2MG0L  [2520]
MTG1  MHOLE  [MTGH200C125D_PL]
MTG2  MHOLE  [MTGH200C125D_PL]
MTG3  MHOLE  [MTGH200C125D_PL]
MTG4  MHOLE  [MTGH200C125D_PL]
R1  100K,1%  [402]
R3  1.5K,1%  [402]
R4  1.5K,1%  [402]
R5  0,1%  [402]
R6  0,1%  [402]
R7  0,1%  [402]
R8  0,1%  [402]
R9  0,1%,DNI  [402]
R10  470K,1%  [402]
R11  280K,1%  [402]
R12  4.75K,5%  [402]
R168  0R,1% DNP  [402]
S3  SMD Button Top  [SW_4P]
TP1  TESTPT1  [tp1-8040]
TP5  TESTPT1  [TP60C33D]
TP6  TESTPT1  [TP60C33D]
TP7  TESTPT1  [TP60C33D]
TP8  TESTPT1  [TP60C33D]
U2  TPS65217C  [U_48_RSL]
U4  TL5209  [SO8-25X75]
sheet P03_AM335x 1/3, JTAG
C21  18pF,50V  [402]
C22  18pF,50V  [402]
C24  2.2uF,6.3V  [402]
C25  18pF,50V  [402]
C26  18pF,50V  [402]
C28  0.1uf,6.3V  [402]
C29  0.1uf,6.3V  [402]
C30  0.1uf,6.3V  [402]
C158  0.1uf,6.3V  [402]
C159  0.1uf,6.3V  [402]
P2  CTI JTAG,DNI  [HEADER10X2_SMD]
R14  10K,1%  [402]
R17  1M,1%  [402]
R18  33  [0402]
R19  0,1%  [402]
R20  0,1%  [402]
R22  49.9,1%  [402]
R23  4.75K,1%  [402]
R24  4.75K,1%  [402]
R25  4.75K,1%  [402]
R29  0,1%  [402]
R30  0,1%  [402]
R160  0,1%  [402]
R161  0,1%  [402]
R162  0,1%  [402]
R167  33  [0402]
R169  0,1% DNP  [402]
R170  0,1% DNP  [402]
R171  4.75K,5%  [402]
R172  4.75K,5%  [402]
R173  4.75K,5%  [402]
R174  4.75K,5%,DNP  [402]
R175  4.75K,5%.DNP  [402]
S1  SMD Button Top  [SW_4P]
U3  SN74LVC1G06DCK  [DCK5_2P15X1P4]
U16  SN74LVC1G07DCK  [DCK5_2P15X1P4]
U17  SSDCI3128AF  [TDFN8_P5_2P0]
Y1  32.768KHz MC-306  [XTAL4_126-216SMD]
Y2  24MHz  [XTAL150SMD_125X196]
Y4  24.576MHZ  [OSC4_61X65LS_79X98SMD]
sheet P04_AM335x 2/3, USB
C31  0.1uf,6.3V  [402]
C32  0.001uf,50V  [402]
C33  0.1uf,6.3V  [402]
C34  100uF,6.3V  [RD205SMD_250D]
C35  0.1uf,6.3V  [402]
C36  0.1uf,6.3V  [402]
C155  0.1uf,6.3V  [402]
FB7  150OHM800mA  [sm-7351-ind-0805]
FB8  0.1R,0805  [sm-7351-ind-0805]
J1  HEADER 6  [SIP6]
P3  DIP USB A TYPE FMAL  [USB-003A-4P-90D]
P4  SMD Micro USB-B-without POST-W/P  [5P-USB-B]
R26  4.75K,1%  [402]
R27  0,1%  [402]
R28  33  [0402]
R45  22  [0402]
R46  0  [0402]
R47  0  [0402]
R48  0  [0402]
R49  0,1%  [402]
R50  0,1%  [402]
R51  0,1%  [402]
R52  10K,1%  [402]
R53  10K,1%  [402]
R159  0,1%  [402]
R163  4.75K,1%  [402]
R164  4.75K,1%  [402]
R165  100K,1%  [402]
TP9  TESTPT1  [TP60C33D]
U8  TPS2051 (DGN)  [DGN-16X60]
U9  TPD4S012  [U_6_DRY]
U10  TPD4S012  [U_6_DRY]
U15  SN74LVC2G241  [U_8_DCU]
sheet P05_AM335x 3/3
C37  0.1uf,6.3V  [402]
C38  0.1uf,6.3V  [402]
C39  10uF,10V  [805]
C40  10uF,10V  [805]
C41  0.1uf,6.3V  [402]
C42  0.1uf,6.3V  [402]
C43  0.1uf,6.3V  [402]
C44  0.1uf,6.3V  [402]
C45  0.1uf,6.3V  [402]
C46  0.1uf,6.3V  [402]
C47  0.1uf,6.3V  [402]
C48  0.1uf,6.3V  [402]
C49  0.1uf,6.3V  [402]
C50  0.1uf,6.3V  [402]
C51  0.1uf,6.3V  [402]
C52  0.1uf,6.3V  [402]
C53  0.1uf,6.3V  [402]
C54  0.1uf,6.3V  [402]
C55  10uF,10V  [805]
C56  0.1uf,6.3V  [402]
C57  0.1uf,6.3V  [402]
C58  0.1uf,6.3V  [402]
C59  0.1uf,6.3V  [402]
C60  0.1uf,6.3V  [402]
C61  0.1uf,6.3V  [402]
C62  10uF,10V  [805]
C63  0.1uf,6.3V  [402]
C64  0.1uf,6.3V  [402]
C65  0.1uf,6.3V  [402]
C66  0.1uf,6.3V  [402]
C67  0.1uf,6.3V  [402]
C68  0.1uf,6.3V  [402]
C69  0.1uf,6.3V  [402]
C70  0.1uf,6.3V  [402]
C71  0.1uf,6.3V  [402]
C72  0.1uf,6.3V  [402]
C73  0.1uf,6.3V  [402]
C74  0.1uf,6.3V  [402]
C75  0.1uf,6.3V  [402]
C76  0.1uf,6.3V  [402]
C77  10uF,10V  [805]
C78  0.1uf,6.3V  [402]
C79  0.1uf,6.3V  [402]
C80  0.1uf,6.3V  [402]
C81  0.1uf,6.3V  [402]
C82  0.1uf,6.3V  [402]
C83  0.1uf,6.3V  [402]
C84  0.1uf,6.3V  [402]
C85  0.1uf,6.3V  [402]
C86  0.1uf,6.3V  [402]
C87  0.1uf,6.3V  [402]
C88  0.1uf,6.3V  [402]
C89  1uF,10V  [402]
C90  1uF,10V  [402]
C91  1uF,10V  [402]
C92  0.1uf,6.3V  [402]
C93  0.1uf,6.3V  [402]
C94  0.1uf,6.3V  [402]
C95  10uF,10V  [805]
C96  10uF,10V  [805]
C97  0.1uf,6.3V  [402]
C98  0.1uf,6.3V  [402]
C99  0.1uf,6.3V  [402]
C100  0.1uf,6.3V  [402]
C101  0.1uf,6.3V  [402]
C102  0.1uf,6.3V  [402]
C103  0.1uf,6.3V  [402]
C104  1uF,10V  [402]
C105  0.1uf,6.3V  [402]
C106  1uF,10V  [402]
FB1  150OHM800mA  [sm-7351-ind-0805]
FB2  150OHM800mA  [sm-7351-ind-0805]
FB3  150OHM800mA  [sm-7351-ind-0805]
R54  10K,1%  [402]
TP2  TESTPT1  [TP60C_SMD]
TP3  TESTPT1  [TP60C_SMD]
U5  AM3358BZCZ100  [am33xx_15x15]  (sections A,B,C)
sheet P06_LED, Config
D2  LTST-C191TBKT  [LED_0603]
D3  LTST-C191TBKT  [LED_0603]
D4  LTST-C191TBKT  [LED_0603]
D5  LTST-C191TBKT  [LED_0603]
Q1  DMC56404  [SMini6-F3-B]  (sections A,B)
Q2  DMC56404  [SMini6-F3-B]  (sections A,B)
R55  100K,1%,DNI  [402]
R56  100K,1%  [402]
R57  100K,1%,DNI  [402]
R58  100K,1%,DNI  [402]
R59  100K,1%,DNI  [402]
R60  100K,1%,DNI  [402]
R61  100K,1%,DNI  [402]
R62  100K,1%,DNI  [402]
R63  100K,1%,DNI  [402]
R64  100K,1%,DNI  [402]
R65  100K,1%  [402]
R66  100K,1%  [402]
R67  100K,1%  [402]
R68  100K,1%  [402]
R69  100K,1%,DNI  [402]
R70  100K,1%,DNI  [402]
R71  4.75K,5%  [402]
R72  4.75K,5%  [402]
R73  4.75K,5%  [402]
R74  4.75K,5%  [402]
R75  100,1%  [402]
R76  100K,1%  [402]
R77  100K,1%  [402]
R78  100K,1%  [402]
R79  100K,1%  [402]
R80  100K,1%  [402]
R81  100K,1%,DNI  [402]
R82  100K,1%  [402]
R83  100K,1%  [402]
R84  100K,1%  [402]
R85  100K,1%  [402]
R86  100K,1%  [402]
R87  100K,1%  [402]
R88  100K,1%  [402]
R89  100K,1%  [402]
R90  100K,1%,DNI  [402]
R91  100K,1%,DNI  [402]
R92  100K,1%,DNI  [402]
R93  100K,1%,DNI  [402]
R94  100K,1%  [402]
R95  100K,1%  [402]
S2  SMD Button Top  [SW_4P]
sheet P07_DDR3 Memory
C107  0.1uf,6.3V  [402]
C108  0.1uf,6.3V  [402]
C109  0.1uf,6.3V  [402]
C110  0.1uf,6.3V  [402]
C111  0.1uf,6.3V  [402]
C112  0.1uf,6.3V  [402]
C113  0.1uf,6.3V  [402]
C114  0.1uf,6.3V  [402]
C115  0.1uf,6.3V  [402]
C116  0.1uf,6.3V  [402]
C117  0.1uf,6.3V  [402]
C118  10uF,10V  [805]
C119  0.1uf,6.3V  [402]
C120  0.1uf,6.3V  [402]
C121  0.1uf,6.3V  [402]
C122  10uF,10V  [805]
C123  0.001uf,50V  [402]
C124  0.1uf,6.3V  [402]
R96  10K,1%  [402]
R97  1.5K,1%  [402]
R98  10K,1%  [402]
R99  240  [SM-7351-RES-0402]
R100  10K,1%  [402]
U12  MT41K256M16HA -125:E  [BGA96_T9_P8_9X14]
sheet P08_eMMC FLASH
C125  2.2uF,6.3V  [402]
C126  10uF,10V  [805]
C127  0.1uf,6.3V  [402]
C128  0.1uf,6.3V  [402]
C129  0.1uf,6.3V  [402]
C130  0.1uf,6.3V  [402]
R101  10K,1%  [402]
R102  10K,1%  [402]
R103  10K,1%  [402]
R104  10K,1%  [402]
R105  10K,1%  [402]
R106  10K,1%  [402]
R107  10K,1%  [402]
R108  10K,1%  [402]
R109  10K,1%  [402]
R110  10K,1%  [402]
R111  10K,1%  [402]
U13  MEM_MNAND_4GB  [BGA153_P14_P5_11P5X13]
sheet P09_10/100 Ethernet
C131  0.1uf,6.3V  [402]
C132  0.1uf,6.3V  [402]
C133  10uF,10V  [805]
C134  1uF,10V  [402]
C135  0.1uf,6.3V  [402]
C136  470pF,6.3V  [0402]
C137  33pF,4 EMI  [402]
C138  33pF,4 EMI  [402]
C139  33pF,4 EMI  [402]
C140  33pF,4 EMI  [402]
C141  0.022uF,10V  [402]
C142  30pF,50V  [402]
C143  30pF,50V  [402]
C161  33pF,4 EMI  [402]
C162  33pF,4 EMI  [402]
C163  100pF,4 EMI  [402]
C164  100pF,4 EMI  [402]
C165  100nF,4 EMI  [402]
C166  100nF,4 EMI  [402]
FB4  150OHM800mA  [sm-7351-ind-0805]
P5  LPJ0011BBNL  [RJ45-7499010211A]
R112  1.5K,1%  [402]
R113  1.5K,1%  [402]
R114  1.5K,1%  [402]
R115  10K,1%  [402]
R116  10K,1%  [402]
R117  10K,1%  [402]
R118  10K,1%  [402]
R119  1.5K,1%  [402]
R120  49.9,1%  [402]
R121  49.9,1%  [402]
R122  49.9,1%  [402]
R123  49.9,1%  [402]
R124  10,1%,DNI  [402]
R125  100,1%  [402]
R126  100,1%  [402]
R127  100,1%  [402]
R128  100,1%  [402]
R129  100,1%  [402]
R130  470,5%  [402]
R131  100,1%  [402]
R132  470,5%  [402]
R133  100,1%  [402]
R134  100,1%  [402]
R135  10K,1%  [402]
R136  0.1R,0805  [805]
R137  0,1%  [402]
R138  100,1%  [402]
R139  100,1%  [402]
R140  0,1%,DNI  [402]
R141  1M,1%,DNI  [402]
R142  0,1%  [402]
R143  10,1%  [402]
R144  12.1K,1%  [402]
R145  10K,1%  [402]
U14  LAN8710A  [QFN32_5X5MM_EP3P3MM]
Y3  25.000MHz  [XTAL150SMD_125X196]
sheet P10_Exp Conn, uSD
C152  0.1uf,6.3V  [402]
C153  10uF,10V  [805]
C154  0.1uf,6.3V  [402]
J4  GroveHDR  [4P-SMD-2_0-90D]
J5  GroveHDR  [4P-SMD-2_0-90D]
P8  FEMALE HEADER 2x23  [HEADER23X2]
P9  FEMALE HEADER 2x23  [HEADER23X2]
P10  SCHA5B0200  [SD-MICRO-SCHA5B0300]
R150  10K,1%  [402]
R151  10K,1%  [402]
R152  10K,1%  [402]
R153  10K,1%  [402]
R154  10K,1%  [402]
R155  10K,1%  [402]
R156  10K,1%  [402]
R157  10K,1%  [402]
TP4  TESTPT1  [tp1-8040]
U7  24LC32A  [SOT23-5]

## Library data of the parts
C1 C2 C4 C7-C15 C39 C40 C55 C62 C77 C95 C96 C118 C122 C126 C133 C153 = CAP_10uF_Y5V_10V_10%_0805
C3 C20 C28-C31 C33 C35-C38 C41-C54 C56-C61 C63-C76 C78-C88 C92-C94 C97-C103 C105 C107-C117 C119-C121 C124 C127-C132 C135 C152 C154 C155 C158 C159 = CAP_0.1uF_X5R_6.3V_20%_0201
C16-C18 C125 = CAP_2.2uF_X5R_6.3V_10%_0402
C19 = CAP_470PF_X7R_25V_10%_0402
D1-D5 = LED_LTST-C150GKT_0
L1-L3 = IND_2.2uH_2.6A_10%_SMD
MTG1-MTG4 = MHOLE
R1 R49 R55-R70 R75-R95 R165 = RES_100K_1_16W_1%_0402
R3 R4 R119 R168 = RES_1.5K_1_16W_5%_0402
R5-R9 R23-R26 R50 R51 R112-R118 R159-R164 R169 R170 = RES_4.75K_1_16W_1%_0402
R10-R12 R71-R74 R130 R132 R171-R175 = RES_470_1_10W_5%_0402
S1 S3 = SW_KT11P2JM_2
TP1-TP9 = TESTPT1
U2 = PWR_TPS65217_2
U4 = PWR_TLV70233DBV_0
C21 C22 C25 C26 = CAP_18PF_COG_50V_5%_0402
C24 C89-C91 C104 C106 C134 = CAP_1.0UF_X5R_10V_10%_0402
P2 = HDR_10x2_CJTAG_0
R14 R52-R54 R96-R98 R100-R111 R135 R137 R143 R145 R150-R155 R157 = RES_10K_1_16W_1%_0402
R17 R141 = RES_1M_1_16W_1%_0402
R18 R28 R45-R48 R167 = RES_33_0402: Part Number: RES_33_0201
R19 R20 R27 R29 R30 R140 R142 R156 = RES_0_1_16W_1%_0402
R22 R120-R123 = RES_4.7K_0402
U3 = IC_SN74LVC1G06DCK_0
U16 = IC_SN74LVC1G07DCK
U17 = SSDCI3128AF
Y1 = CRYS_32_768KHz_SMD32_1
Y2 = CRYS_24MHz_SCC_0
Y4 = OSC_12MHz_1.3V
C32 C123 = CAP_0.001_X7R_50V_5%_0402
C34 = CAP_100UF_TANT_6.3V_3528-21
FB1-FB4 FB7 FB8 = FER_180_200_0
J1 = HEADER_6
P3 = CONN_54819-0578_2
P4 = MINI-USB-AB-SOCKET
U8 = TPS2061_1
U9 U10 = PROT_TPD4S012
U15 = IC_SN74LVC2G241_1
U5 = IC_AM335X_ZCZ
Q1 Q2 = RN1907: ATLStockNo2: 2130.01
S2 = SW_KT11P2JM_1
R99 = Res: Res, 240E, 1%, Thick Film, 0.1W, SMD, Size 0402; Created By: Sankar; Created Date: 4/12/2010; DescriptiveText: RES 240 OHM 1/10W 1% 0402 SMD; Mfg: KOA; Mfr: Panasonic-ECG; MfrNum: ERJ-2RKF2400X; PartName: 240E1/10W1%smd0402; Sub_Type: Thick Film; Tolerance: 1%
U12 = MT47H256M8_7: DescriptiveText: DDR3 Memory 4Gb; Mfr: Micron; MfrNum: MT41J256M16RE-15E; PartName: MT41J256M16RE-15E
U13 = MEM_MNAND_2GB
C136 = 470pF_5%_50V_C0G_0603_0
C137-C140 C161-C166 = CAP_0402_100pF_COG_50V
C141 = CAP_0402_0.1uf_X5R_10V
C142 C143 = CAP_30PF_COG_50V_5%_0402
P5 = CONN_RJ45_MAG_WE_0
R124-R126 R129 R134 R138 = 100-1_10W-1%-0603_4
R127 R128 R131 R133 R139 = RES_100_1_10W_5%_0402
R136 = RES_0.1_0805
R144 = RES_12.1K_1_16W_1%_0402
U14 = LAN8710_QFN32_1
Y3 = Suntsu_ITEMP_25MHz__0.005%_20pf
J4 J5 = HEADER_4
P8 P9 = HDR_46_F_2_0.1_0.1
P10 = microSD_CONN_8
U7 = MEM_24LC32_SOT23-5

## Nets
DGND: C1.1 C2.1 C3.1 C4.1 C7.1 C8.1 C9.1 C10.1 C11.1 C12.1 C13.1 C14.1 C15.1 C16.2 C17.2 C18.2 C19.2 C20.2 C24.2 C28.2 C29.2 C30.2 C34.2 C35.2 C36.2 C37.2 C38.2 C39.1 C40.1 C41.2 C42.2 C43.2 C44.2 C45.2 C46.2 C47.2 C48.2 C49.2 C50.2 C51.2 C52.2 C53.2 C54.2 C55.1 C56.1 C57.1 C58.2 C59.2 C60.1 C61.1 C62.1 C63.2 C64.2 C65.2 C66.2 C67.2 C68.1 C69.1 C70.1 C71.1 C72.1 C73.1 C74.1 C75.1 C76.1 C77.2 C78.2 C79.2 C80.2 C81.2 C82.2 C83.2 C84.2 C85.2 C86.2 C87.2 C88.2 C89.2 C90.2 C91.2 C92.2 C94.2 C95.1 C96.1 C97.2 C98.2 C99.2 C100.2 C101.2 C102.2 C103.2 C104.2 C105.2 C106.2 C107.2 C108.2 C109.2 C110.2 C111.2 C112.2 C113.2 C114.2 C115.2 C116.2 C117.2 C118.1 C119.2 C120.2 C121.2 C122.1 C123.2 C124.2 C125.2 C126.1 C127.2 C128.2 C129.2 C130.2 C131.2 C132.2 C133.1 C134.2 C135.2 C136.2 C137.2 C138.2 C139.2 C140.2 C141.2 C142.2 C143.2 C152.2 C153.2 C154.2 C155.1 C158.2 C159.2 C161.2 C162.1 FB3.2 J1.1 J4.4 J5.4 P2.4(TDIS) P2.8(GND1) P2.10(GND2) P2.12(GND3) P2.16(GND4) P2.20(GND5) P3.4(P4) P4.5(G1) P5.8(GND) P8.1 P8.2(26) P9.1 P9.2(26) P9.43(22) P9.44(47) P9.45(23) P9.46(48) P10.6(VSS) P10.9(GND) Q1.1(4) Q1.4 Q2.1(4) Q2.4 R10.2 R12.1 R22.1 R25.2 R29.1 R30.1 R49.1 R53.2 R54.1 R76.2 R77.2 R78.2 R79.2 R80.2 R81.2 R82.2 R83.2 R84.2 R85.2 R86.2 R87.2 R88.2 R89.2 R90.2 R91.2 R92.2 R93.2 R94.2 R95.2 R96.1 R99.1 R100.2 R115.2 R116.2 R117.2 R118.2 R130.1 R132.1 R135.2 R136.1 R144.2 R145.2 R164.2 R165.2 R170.2 S1.1(A1) S1.3(A2) S2.2(B1) S2.4(B2) S3.1(A1) S3.3(A2) TP1.1(TP) TP8.1(TP) U2.30(PGND) U2.41(AGND) U2.49(PPAD) U3.3(GND) U4.5(GND1) U4.6(GND3) U4.7(GND2) U4.8(GND4) U5.A1(VSS1) U5.A18(VSS2) U5.F8(VSS3) U5.G8(VSS4) U5.G9(VSS5) U5.G11(VSS6) U5.G12(VSS7) U5.H6(VSS8) U5.H7(VSS9) U5.H8(VSS10) U5.H9(VSS11) U5.H10(VSS12) U5.H12(VSS13) U5.J6(VSS14) U5.J7(VSS15) U5.J8(VSS16) U5.J9(VSS17) U5.J10(VSS18) U5.J11(VSS19) U5.K7(VSS20) U5.K9(VSS21) U5.K10(VSS22) U5.K11(VSS23) U5.L10(VSS24) U5.L11(VSS25) U5.L12(VSS26) U5.L13(VSS27) U5.M6(VSS28) U5.M7(VSS29) U5.M8(VSS30) U5.M9(VSS31) U5.M10(VSS32) U5.M12(VSS33) U5.M14(VSSA_USB2) U5.N7(VSS34) U5.N10(VSS35) U5.N11(VSS36) U5.N14(VSSA_USB1) U5.V1(VSS37) U5.V18(VSS38) U7.2(VSS) U8.1(GND) U8.9(PAD) U9.4(GND) U10.4(GND) U12.A9(VSS1) U12.B1(VSSQ1) U12.B3(VSS2) U12.B9(VSSQ2) U12.D1(VSSQ3) U12.D8(VSSQ4) U12.E1(VSS3) U12.E2(VSSQ5) U12.E8(VSSQ6) U12.F9(VSSQ7) U12.G1(VSSQ8) U12.G8(VSS4) U12.G9(VSSQ9) U12.J2(VSS5) U12.J8(VSS6) U12.M1(VSS7) U12.M9(VSS8) U12.P1(VSS9) U12.P9(VSS10) U12.T1(VSS11) U12.T9(VSS12) U13.C4(VSSQ4) U13.E7(VSS2) U13.G5(VSS1) U13.H10(VSS3) U13.K8(VSS4) U13.N2(VSSQ1) U13.N5(VSS5) U13.P4(VSSQ3) U13.P6(VSSQ2) U14.33(GND_EP) U15.1(~{1OE}) U15.4(GND) U16.3(GND) Y4.2(GND)
GND_EARTH: C163.2 C164.2 C165.2 C166.2 MTG1.1(TP) MTG2.1(TP) MTG3.1(TP) MTG4.1(TP) P3.5(SHELD1) P3.6(PAD4) P4.6(G3) P4.7(G2) P4.8(G5) P4.9(G4) P5.13(SHD1) P5.14(SHD2) P10.11(GND3) P10.12(GND4) P10.13(GND5) P10.14(GND6) P10.15(GND7) P10.16(GND8) R136.2
GND_OSC0: C25.2 C26.2 R29.2 R173.2 R174.2 U5.V11(VSS_OSC0) U17.4(GND)
GND_OSC1: C21.1 C22.1 R30.2 U5.A5(VSS_RTC)
GNDA_ADC: C31.2 C32.2 C33.2 C93.2 FB3.1 P9.34(42) U5.A9(VREFN) U5.E8(VSSA_ADC)
VBUS: FB7.2 P3.1(P1)
VDD_1V8: C14.2 C78.1 C86.1 C88.1 FB1.1 FB2.2 R9.2 U2.40(LDO3) U5.D10(VDDS_SRAM_MPU_BB) U5.E9(VDDS_SRAM_CORE_BG) U5.N16(VDDA1P8V_USB0) U5.R16(VDDA1P8V_USB1)
VDD_3V3A: C15.2 C37.1 C38.1 C56.2 C57.2 C58.1 C59.1 C60.2 C61.2 C66.1 C67.1 C68.2 C69.2 C70.2 C71.2 C72.2 C73.2 C74.2 C75.2 C76.2 C77.1 C87.1 C152.1 C158.1 C159.1 R1.1 R3.1 R4.1 R14.1 R52.1 R55.1 R56.1 R57.1 R58.1 R59.1 R60.1 R61.1 R62.1 R63.1 R64.1 R65.1 R66.1 R67.1 R68.1 R69.1 R70.1 R156.1 R169.2 R171.1 R172.1 R175.1 U2.43(LDO4) U3.5(VCC) U4.1(EN) U5.E10(VDDSHV61) U5.E11(VDDSHV62) U5.E12(VDDSHV63) U5.E13(VDDSHV64) U5.F14(VDDSHV65) U5.G14(VDDSHV66) U5.H14(VDDSHV41) U5.J14(VDDSHV42) U5.K14(VDDSHV51) U5.L14(VDDSHV52) U5.N5(VDDSHV67) U5.N15(VDDA3P3V_USB0) U5.P5(VDDSHV68) U5.P6(VDDSHV69) U5.P7(VDDSHV11) U5.P8(VDDSHV12) U5.P10(VDDSHV21) U5.P11(VDDSHV22) U5.P12(VDDSHV31) U5.P13(VDDSHV32) U5.R15(VDDA3P3V_USB1) U7.4(VCC) U17.8(VDD) Y4.4(VCC)
VDD_3V3AUX: C18.1 D1.2(A) U2.1(VLDO2)
VDD_3V3B: C20.1 C29.1 C126.2 C127.1 C128.1 C129.1 C130.1 C135.1 C153.1 C154.1 C155.2 FB4.1 J4.3 J5.3 P2.5(TVDD) P9.3(2) P9.4(27) P10.4(VDD) R11.1 R23.1 R24.1 R101.1 R102.1 R103.1 R104.1 R105.1 R106.1 R107.1 R108.1 R109.1 R110.1 R111.1 R112.2 R113.2 R114.2 R119.1 R150.1 R151.1 R152.1 R153.1 R154.1 R155.1 R157.2 R163.1 U4.3(OUT) U13.C6(VCCQ4) U13.E6(VCC3) U13.F5(VCC2) U13.J10(VCC0) U13.K9(VCC1) U13.M4(VCCQ5) U13.N4(VCCQ3) U13.P3(VCCQ1) U13.P5(VCCQ2) U14.12(VDDIO) U15.7(2OE) U15.8(VCC)
VDD_5V: C2.2 P9.5(3) P9.6(28) R168.2 U2.10(AC)
VDD_ADC: C93.1 FB2.1 P9.32(41) R27.1 U5.D8(VDDA_ADC)
VDD_CORE: C11.2 C39.2 C40.2 C41.1 C42.1 C43.1 C44.1 C45.1 C46.1 C47.1 C48.1 C49.1 C50.1 C51.1 C52.1 C53.1 C54.1 C55.2 L3.2 U2.29(VDCDC3) U5.F6(VDD_CORE1) U5.F7(VDD_CORE2) U5.G6(VDD_CORE3) U5.G7(VDD_CORE4) U5.G10(VDD_CORE5) U5.H11(VDD_CORE6) U5.J12(VDD_CORE7) U5.K6(VDD_CORE8) U5.K8(VDD_CORE9) U5.K12(VDD_CORE10) U5.L6(VDD_CORE11) U5.L7(VDD_CORE12) U5.L8(VDD_CORE13) U5.L9(VDD_CORE14) U5.M11(VDD_CORE15) U5.M13(VDD_CORE16) U5.N8(VDD_CORE17) U5.N9(VDD_CORE18) U5.N12(VDD_CORE19) U5.N13(VDD_CORE20)
VDD_MPU: C12.2 C62.2 C63.1 C64.1 C65.1 L2.2 U2.24(VDCDC2) U5.F10(VDD_MPU1) U5.F11(VDD_MPU2) U5.F12(VDD_MPU3) U5.F13(VDD_MPU4) U5.G13(VDD_MPU5) U5.H13(VDD_MPU6) U5.J13(VDD_MPU7)
VDD_MPUON: TP2.1(TP) U5.A2(VDD_MPU_MON)
VDD_PHYA: C131.1 C132.1 C133.2 FB4.2 R120.2 R121.2 R122.2 R123.2 R137.2 U14.1(VDD2A) U14.27(VDD1A)
VDD_PLL: C79.1 C92.1 C94.1 C106.1 FB1.2 U5.E7(VDDS_PLL_DDR) U5.H15(VDDS_PLL_MPU) U5.R10(VDDS_PLL_CORE_LCD) U5.R11(VDDS_OSC)
VDD_RTC: C104.1 U5.D6(CAP_VDD_RTC)
VDDS: C80.1 C81.1 C82.1 C83.1 C84.1 C85.1 R8.2 R9.1 U5.E6(VDDS1) U5.E14(VDDS2) U5.F9(VDDS3) U5.K13(VDDS4) U5.N6(VDDS5) U5.P9(VDDS6) U5.P14(VDDS7)
VDDS_DDR: C9.2 C95.2 C96.2 C97.1 C98.1 C99.1 C100.1 C101.1 C102.1 C103.1 C107.1 C108.1 C109.1 C110.1 C111.1 C112.1 C113.1 C114.1 C115.1 C116.1 C117.1 C118.2 C119.1 C120.1 C121.1 C122.2 R6.2 R97.1 R98.1 U5.E5(VDDS_DDR1) U5.F5(VDDS_DDR2) U5.G5(VDDS_DDR3) U5.H5(VDDS_DDR4) U5.J5(VDDS_DDR5) U5.K5(VDDS_DDR6) U5.L5(VDDS_DDR7) U12.A1(VDDQ1) U12.A8(VDDQ2) U12.B2(VDD1) U12.C1(VDDQ3) U12.C9(VDDQ4) U12.D2(VDDQ5) U12.D9(VDD9) U12.E9(VDDQ7) U12.F1(VDDQ8) U12.G7(VDD2) U12.H2(VDDQ9) U12.H9(VDDQ10) U12.K2(VDD4) U12.K8(VDD5) U12.N1(VDD6) U12.N9(VDD7) U12.R1(VDD8) U12.R9(VDD3)
AIN0: P9.39(20) U5.B6(AIN0)
AIN1: P9.40(45) U5.C7(AIN1)
AIN2: P9.37(19) U5.B7(AIN2)
AIN3: P9.38(44) U5.A7(AIN3)
AIN4: P9.33(17) U5.C8(AIN4)
AIN5: P9.36(43) U5.B8(AIN5)
AIN6: P9.35(18) U5.A8(AIN6)
AIN7: R163.2 R164.1 U5.C9(AIN7)
B_UART0_RX: J1.4 R165.1 U15.2(1A)
B_UART0_TX: J1.5 U15.3(2Y)
CAP_VBB_MPU: C91.1 U5.C10(CAP_VBB_MPU)
CAP_VDD_SRAM_CORE: C89.1 U5.D9(CAP_VDD_SRAM_CORE)
CAP_VDD_SRAM_MPU: C90.1 U5.D11(CAP_VDD_SRAM_MPU)
CLKOUT2: P2.18(EMU3) P9.41(21) R19.2 R20.1
CLKOUT_SRC: R19.1 U5.D14(EVENT_INTR1/TCLKIN/CLKOUT2/TIMER7/PR1PRU0_PRUR31_16/EMU3/GPIO0_20)
CRS: R139.2 U14.14(CRS)
DDR_A0: U5.F3(DDR_A0) U12.N3(A0)
DDR_A1: U5.H1(DDR_A1) U12.P7(A1)
DDR_A2: U5.E4(DDR_A2) U12.P3(A2)
DDR_A3: U5.C3(DDR_A3) U12.N2(A3)
DDR_A4: U5.C2(DDR_A4) U12.P8(A4)
DDR_A5: U5.B1(DDR_A5) U12.P2(A5)
DDR_A6: U5.D5(DDR_A6) U12.R8(A6)
DDR_A7: U5.E2(DDR_A7) U12.R2(A7)
DDR_A8: U5.D4(DDR_A8) U12.T8(A8)
DDR_A9: U5.C1(DDR_A9) U12.R3(A9)
DDR_A10: U5.F4(DDR_A10) U12.L7(A10)
DDR_A11: U5.F2(DDR_A11) U12.R7(A11)
DDR_A12: U5.E3(DDR_A12) U12.N7(A12)
DDR_A13: U5.H3(DDR_A13) U12.T3(A13)
DDR_A14: U5.H4(DDR_A14) U12.T7(A14)
DDR_A15: U5.D3(DDR_A15) U12.M7(A15)
DDR_BA0: U5.C4(DDR_BA0) U12.M2(BA0)
DDR_BA1: U5.E1(DDR_BA1) U12.N8(BA1)
DDR_BA2: U5.B3(DDR_BA2) U12.M3(BA2)
DDR_CASn: U5.F1(DDR_CASN) U12.K3(CASn)
DDR_CKE: R96.2 U5.G3(DDR_CKE) U12.K9(CKE)
DDR_CLK: U5.D2(DDR_CK) U12.J7(CK)
DDR_CLKn: U5.D1(DDR_NCK) U12.K7(CKn)
DDR_CSn: U5.H2(DDR_CSN0) U12.L2(CSn)
DDR_D0: U5.M3(DDR_D0) U12.E3(DQ0)
DDR_D1: U5.M4(DDR_D1) U12.F7(DQ1)
DDR_D2: U5.N1(DDR_D2) U12.F2(DQ2)
DDR_D3: U5.N2(DDR_D3) U12.F8(DQ3)
DDR_D4: U5.N3(DDR_D4) U12.H3(DQ4)
DDR_D5: U5.N4(DDR_D5) U12.H8(DQ5)
DDR_D6: U5.P3(DDR_D6) U12.G2(DQ6)
DDR_D7: U5.P4(DDR_D7) U12.H7(DQ7)
DDR_D8: U5.J1(DDR_D8) U12.D7(DQ8)
DDR_D9: U5.K1(DDR_D9) U12.C3(DQ9)
DDR_D10: U5.K2(DDR_D10) U12.C8(DQ10)
DDR_D11: U5.K3(DDR_D11) U12.C2(DQ11)
DDR_D12: U5.K4(DDR_D12) U12.A7(DQ12)
DDR_D13: U5.L3(DDR_D13) U12.A2(DQ13)
DDR_D14: U5.L4(DDR_D14) U12.B8(DQ14)
DDR_D15: U5.M1(DDR_D15) U12.A3(DQ15)
DDR_DQM0: U5.M2(DDR_DQM0) U12.E7(LDM)
DDR_DQM1: U5.J2(DDR_DQM1) U12.D3(UDM)
DDR_DQS0: U5.P1(DDR_DQS0) U12.F3(LDQS)
DDR_DQS1: U5.L1(DDR_DQS1) U12.C7(UDQS)
DDR_DQSN0: U5.P2(DDR_DQSN0) U12.G3(LDQSn)
DDR_DQSN1: U5.L2(DDR_DQSN1) U12.B7(UDQSn)
DDR_ODT: U5.G1(DDR_ODT) U12.K1(ODT)
DDR_RASn: U5.G4(DDR_RASN) U12.J3(RASn)
DDR_RESETn: R97.2 U5.G2(DDR_RESETN) U12.T2(RESET#)
DDR_VREF: C28.1 C123.1 C124.1 R98.2 R100.1 U5.J4(VREFSSTL) U12.H1(VREF_DQ) U12.M8(VREF_CA)
DDR_VTP: R22.2 U5.J3(DDR_VTP)
DDR_WEn: U5.B2(DDR_WEn) U12.L3(WEn)
EHRPWM1A: P9.14(32) U5.U14(GPMC_A2/GMII2_TXD3/RGMII2_TD3/MMC2_DAT1/GPMC_A18/PR1_MII1_TXD2/EHRPWM1A/GPIO1_18)
EHRPWM1B: P9.16(33) U5.T14(GPMC_A3/GMII2_TXD2/RGMII2_TD2/MMC2_DAT2/GPMC_A19/PR1_MII1_TXD1/EHRPWM1B/GPIO1_19)
EHRPWM2A: P8.19(10) U5.U10(GPMC_AD8/LCD_DATA23/MMC1_DAT0/MMC2_DAT4/EHRPWM2A/PR1_MII_MT0_CLK//GPIO0_22)
EHRPWM2B: P8.13(7) U5.T10(GPMC_AD9/LCD_DATA22/MMC1_DAT1/MMC2_DAT5/EHRPWM2B/PR1_MII0_CRS//GPIO0_23)
eMMC_RSTn: R111.2 R162.2 U13.K5(~{RST})
eMMC_VCCI: C125.1 U13.C2(VCCI)
ENZ_KALDO_1P8V: R54.2 U5.B4(ENZ_KALDO_1P8V)
ETH_TXD4: R145.1 U14.18(nINT/TXER/TXD4)
GPIO0_7: P9.42(46) R50.1 R51.1
GPIO0_7SRC: R50.2 U5.C18(ECAP0_IN_PWM0_OUT/UART3_TXD/SPI1_CS1/PR1_ECAP0_ECAP_CAPIN_APWM_O/SPI1_SCLK/MMC0_SDWP/XDMA_EVENT_INTR2/GPIO0_7)
GPIO0_26: P8.14(32) U5.T11(GPMC_AD10/LCD_DATA21/MMC1_DAT2/MMC2_DAT6/EHRPWM2_TRIPZONE_INPUT/PR1_MII0_TXEN//GPIO0_26)
GPIO0_27: P8.17(9) U5.U12(GPMC_AD11/LCD_DATA20/MMC1_DAT3/MMC2_DAT7/EHRPWM2_SYNCI_O/PR1_MII0_TXD3//GPIO0_27)
GPIO1_12: P8.12(31) U5.T12(GPMC_AD12/LCD_DATA19/MMC1_DAT4/MMC2_DAT0/EQEP2A_IN/PR1_MII0_TXD2/PR1_PRU0_PRU_R30_14/GPIO1_12)
GPIO1_13: P8.11(6) U5.R12(GPMC_AD13/LCD_DATA18/MMC1_DAT5/MMC2_DAT1/EQEP2B_IN/PR1_MII0_TXD1/PR1_PRU0_PRU_R30_15/GPIO1_13)
GPIO1_14: P8.16(33) U5.V13(GPMC_AD14/LCD_DATA17/MMC1_DAT6/MMC2_DAT2/EQEP2_INDEX/PR1_MII0_TXD0/PR1_PRU0_PRU_R31_14/GPIO1_14)
GPIO1_15: P8.15(8) U5.U13(GPMC_AD15/LCD_DATA16/MMC1_DAT7/MMC2_DAT3/EQEP2_STROBE/PR1_ECAP0_ECAP_CAPIN_APWM_O/PR1_PRU0_PRU_R31_15/GPIO1_15)
GPIO1_16: P9.15(8) R160.2 R161.2
GPIO1_17: P9.23(12) U5.V14(GPMC_A1/GMII2_RXDV/RGMII2_RCTL/MMC2_DAT0/GPMC_A17/PR1_MII1_TXD3/EHRPWM1_SYNCI_O/GPIO1_17)
GPIO1_28: P9.12(31) U5.U18(GPMC_BE1N/GMII2_COL/GPMC_CSN6/MMC2_DAT3/GPMC_DIR/PR1_MII1_RXLINK/MCASP0_ACLKR/GPIO1_28)
GPIO1_29: P8.26(38) U5.V6(GPMC_CSN0/GPIO1_29)
GPIO2_1: P8.18(34) U5.V12(GPMC_CLK/LCD_MEM_CLK/GPMC_WAIT1/MMC2_CLK/PRT1_MII1_TXEN/MCASP0_FSR/GPIO2_1)
GPIO3_18: R51.2 U5.B12(MCASP0_ACLKR/EQEP0A_IN/MCASP0_AXR2/MCASP1_ACLKX/MMC0_SDWP/PR1_PRU0_PRU_R30_4/PR1_PRU0_PRU_R31_4/GPIO3_18)
GPIO3_19: P9.27(14) U5.C13(MCASP0_FSR/EQEP0B_IN/MCASP0_AXR3/MCASP1_FSX/EMU2/PR1_PRU0_PRU_R30_5/PR1_PRU0_PRU_R31_5/GPIO3_19)
GPIO3_20: R20.2 U5.D13(MCASP0_AXR1/EQEP0_INDEX//MCASP1_AXR0/EMU3/PR1_PRU0_PRU_R30_6/PR1_PRU0_PRU_R31_6/GPIO3_20)
GPIO3_21: P9.25(13) R167.2 U5.A14(MCASP0_AHCLKX/EQEP0_STROBE/MCASP0_AXR3/MCASP1_AXR1/EMU4/PR1_PRU0_PRU_R30_7/PR1_PRU0_PRU_R31_7/GPIO3_21)
GRN_C: P5.10(GRNC) R132.2
GRNA: C163.1 C165.1 P5.9(GRNA) U14.3(LED1/REGOFF)
HDMI_INT: R169.1 R170.1 U5.U16(GPMC_A9/GMII2_RXD2/RGMII2_RD2/MMC2_DAT7/GPMC_A25/PR1_MII_MR1_CLK/MCASP0_FSX/GPIO1_25)
HDMICLK_DISn: U5.V17(GPMC_A11/GMII2_RXD0/RGMII2_RD0/RMII2_RXD0/GPMC_A27/PR1_MII1_RXER/MCASP0_AXR1/GPIO1_27) Y4.1(OE)
I2C0_SCL: R3.2 U2.28(SCL) U5.C16(I2C0_SCL/TIMER7/UART2_RTSN/ECAP1_IN_PWM1_OUT////GPIO3_6) U7.1(SCL)
I2C0_SDA: R4.2 U2.27(SDA) U5.C17(I2C0_SDA/TIMER4/UART2_CTSN/ECAP2_IN_PWM2_OUT////GPIO3_5) U7.3(SDA)
I2C1_SCL: P9.17(9) U5.A16(SPI0_CS0/MMC2_SDWP/I2C1_SCL/EHRPWM0_SYNCI_O/PR1_UART0_TXD/PR1_EDIO_DATA_IN1/PR1_EDIO_DATA_OUT1/GPIO0_5)
I2C1_SDA: P9.18(34) U5.B16(SPI0_D1/MMC1_SDWP/I2C1_SDA/EHRPWM0_TRIPZONE_INPUT/PR1_UART0_RXD/PR1_EDIO_DATA_IN0/PR1_EDIO_DATA_OUT0/GPIO0_4)
I2C2_SCL: J4.1 P9.19(10) U5.D17(UART1_RTSN/TIMER5/DCAN0_RX/I2C2_SCL/SPI1_CS1/PR1_UART0_RTS_N/PR1_EDC_LATCH1_IN/GPIO0_13)
I2C2_SDA: J4.2 P9.20(35) U5.D18(UART1_CTSN/TIMER6/DCAN0_TX/I2C2_SDA/SPI1_CS0/PR1_UART0_CTS_N/PR1_EDC_LATCH0_IN/GPIO0_12)
JTAG_EMU0: P2.13(EMU0) R23.2 U5.C14(EMU0/GPIO3_7)
JTAG_EMU1: P2.14(EMU1) R24.2 U5.B14(EMU1/GPIO3_8)
JTAG_TCK: P2.9(TCKRTN) P2.11(TCK) U5.A12(TCK)
JTAG_TDI: P2.3(TDI) U5.B11(TDI)
JTAG_TDO: P2.7(TDO) U5.A11(TDO)
JTAG_TMS: P2.1(TMS) U5.C11(TMS)
JTAG_TRSTn: P2.2(TRSTn) R25.1 U5.B10(NTRST)
LCD_DATA0: P8.45(23) R70.2 R95.1 U5.R1(LCD_DATA0/GPMC_A0//EHRPWM2A//PR1_PRU1_PRU_R30_0/PR1_PRU1_PRU_R31_0/GPIO2_6)
LCD_DATA1: P8.46(48) R69.2 R94.1 U5.R2(LCD_DATA1/GPMC_A1//EHRPWM2B//PR1_PRU1_PRU_R30_1/PR1_PRU1_PRU_R31_1/GPIO2_7)
LCD_DATA2: P8.43(22) R68.2 R75.1 R93.1 U5.R3(LCD_DATA2/GPMC_A2//EHRPWM2_TRIPZONE_INPUT//PR1_PRU1_PRU_R30_2/PR1_PRU1_PRU_R31_2/GPIO2_8)
LCD_DATA3: P8.44(47) R67.2 R92.1 U5.R4(LCD_DATA3/GPMC_A3//EHRPWM2_SYNCI_O//PR1_PRU1_PRU_R30_3/PR1_PRU1_PRU_R31_3/GPIO2_9)
LCD_DATA4: P8.41(21) R66.2 R91.1 U5.T1(LCD_DATA4/GPMC_A4//EQEP2A_IN//PR1_PRU1_PRU_R30_4/PR1_PRU1_PRU_R31_4/GPIO2_10)
LCD_DATA5: P8.42(46) R65.2 R90.1 U5.T2(LCD_DATA5/GPMC_A5//EQEP2B_IN//PR1_PRU1_PRU_R30_5/PR1_PRU1_PRU_R31_5/GPIO2_11)
LCD_DATA6: P8.39(20) R64.2 R89.1 U5.T3(LCD_DATA6/GPMC_A6/PR1_EDIO_DATA_IN6/EQEP2_INDEX/PR1_EDIO_DATA_OUT6/PR1_PRU1_PRU_R30_6/PR1_PRU1_PRU_R31_6/GPIO2_12)
LCD_DATA7: P8.40(45) R63.2 R88.1 U5.T4(LCD_DATA7/GPMC_A7/PR1_EDIO_DATA_IN7/EQEP2_STROBE/PR1_EDIO_DATA_OUT7/PR1_PRU1_PRU_R30_7/PR1_PRU1_PRU_R31_7/GPIO2_13)
LCD_DATA8: P8.37(19) R62.2 R87.1 U5.U1(LCD_DATA8/GPMC_A12/EHRPWM1_TRIPZONE_INPUT/MCASP0_ACLKX/UART5_TXD/PR1_MII0_RXD3/UART2_CTSN/GPIO2_14)
LCD_DATA9: P8.38(44) R61.2 R86.1 U5.U2(LCD_DATA9/GPMC_A13/EHRPWM1_SYNCI_O/MCASP0_FSX/UART5_RXD/PR1_MII0_RXD2/UART2_RTSN/GPIO2_15)
LCD_DATA10: P8.36(43) R60.2 R85.1 U5.U3(LCD_DATA10/GPMC_A14/EHRPWM1A/MCASP0_AXR0//PR1_MII0_RXD1/UART3_CTSN/GPIO2_16)
LCD_DATA11: P8.34(42) R59.2 R84.1 U5.U4(LCD_DATA11/GPMC_A15/EHRPWM1B/MCASP0_AHCLKR/MCASP0_AXR2/PR1_MII0_RXD0/UART3_RTSN/GPIO2_17)
LCD_DATA12: P8.35(18) R58.2 R83.1 U5.V2(LCD_DATA12/GPMC_A16/EQEP1A_IN/MCASP0_ACLKR/MCASP0_AXR2/PR1_MII0_RXLINK/UART4_CTSN/GPIO0_8)
LCD_DATA13: P8.33(17) R57.2 R82.1 U5.V3(LCD_DATA13/GPMC_A17/EQEP1B_IN/MCASP0_FSR/MCASP0_AXR3/PR1_MII0_RXER/UART4_RTSN/GPIO0_9)
LCD_DATA14: P8.31(16) R56.2 R81.1 U5.V4(LCD_DATA14/GPMC_A18/EQEP1_INDEX/MCASP0_AXR1/UART5_RXD/PR1_MII_MR0_CLK/UART5_CTSN/GPIO0_10)
LCD_DATA15: P8.32(41) R55.2 R80.1 U5.T5(LCD_DATA15/GPMC_A19/EQEP1_STROBE/MCASP0_AHCLKX/MCASP0_AXR3/PR1_MII0_RXDV/UART5_RTSN/GPIO0_11)
LCD_DE: P8.30(40) R48.2
LCD_HSYNC: P8.29(15) R47.2
LCD_PCLK: P8.28(39) R45.2
LCD_VSYNC: P8.27(14) R46.2
LCDDE: R48.1 U5.R6(LCD_AC_BIAS_EN/GPMC_A11//PR1_EDIO_DATA_IN5/PR1_EDIO_DATA_OUT5/PR1_PRU1_PRU_R30_11/PR1_PRU1_PRU_R31_11/GPIO2_25)
LCDPCLK: R45.1 U5.V5(LCD_PCLK/GPMC_A10//PR1_EDIO_DATA_IN4/PR1_EDIO_DATA_OUT4/PR1_PRU1_PRU_R30_10/PR1_PRU1_PRU_R31_10/GPIO2_24)
LCDVHYNC: R47.1 U5.R5(LCD_HSYNC/GPMC_A9//PR1_EDIO_DATA_IN3/PR1_EDIO_DATA_OUT3/PR1_PRU1_PRU_R30_9/PR1_PRU1_PRU_R31_9/GPIO2_23)
LCDVSYNC: R46.1 U5.U5(LCD_VSYNC/GPMC_A8//PR1_EDIO_DATA_IN2/PR1_EDIO_DATA_OUT2/PR1_PRU1_PRU_R30_8/PR1_PRU1_PRU_R31_8/GPIO2_22)
LDO_PGOOD: U2.46(LDO_PGOOD) U5.B5(RTC_PORZn)
LEDAA: D2.2(A) R72.2
LEDAC: D2.1(C) Q1.6(3)
LEDBA: D3.2(A) R73.2
LEDBC: D3.1(C) Q1.3
LEDCA: D4.2(A) R74.2
LEDCC: D4.1(C) Q2.6(3)
LEDDA: D5.2(A) R71.2
LEDDC: D5.1(C) Q2.3
MDIO_CLK: U5.M18(MDIO_CLK/TIMER5/UART5_TXD/UART3_RTSN/MMC0_SDWP/MMC1_CLK/MMC2_CLK/GPIO0_1) U14.17(MDC)
MDIO_DATA: R119.2 U5.M17(MDIO_DATA/TIMER6/UART5_RXD/UART3_CTSN/MMC0_SDCD/MMC1_CMD/MMC2_CMD/GPIO0_0) U14.16(MDIO)
MII1_COL: R138.1 U5.H16(GMII1_COL/RMII2_REFCLK/SPI1_SCLK/UART5_RXD/MCASP1_AXR2/MMC2_DAT3/MCASP0_AXR2/GPIO3_0)
MII1_CRS_DV: R139.1 U5.H17(GMII1_CRS/RMII1_CRS_DV/SPI1_D0/I2C1_SDA/MCASP1_ACLKX/UART5_CTSN/UART2_RXD/GPIO3_1)
MII1_REFCLK: R28.2 R124.1 R140.1
MII1_RXCLK: R131.1 U5.L18(GMII1_RXCLK/UART2_TXD/RGMII1_RCLK/MMC0_DAT6/MMC1_DAT1/UART1_DSRN/MCASP0_FSX/GPIO3_10)
MII1_RXD0: R128.1 U5.M16(GMII1_RXD0/RMII1_RXD0/RGMII1_RD0/MCASP1_AHCLKX/MCASP1_AHCLKR/MCASP1_ACLKR/MCASP0_AXR3/GPIO2_21)
MII1_RXD1: R127.1 U5.L15(GMII1_RXD1/RMII1_RXD1/RGMII1_RD1/MCASP1_AXR3/MCASP1_FSR/EQEP0_STROBE/MMC2_CLK/GPIO2_20)
MII1_RXD2: R126.1 U5.L16(GMII1_RXD2/UART3_TXD/RGMII1_RD2/MMC0_DAT4/MMC1_DAT3/UART1_RIN/MCASP0_AXR1/GPIO2_19)
MII1_RXD3: R125.1 U5.L17(GMII1_RXD3/UART3_RXD/RGMII1_RD3/MMC0_DAT5/MMC1_DAT2/UART1_DTRN/MCASP0_AXR0/GPIO2_18)
MII1_RXDV: R129.1 U5.J17(GMII1_RXDV/LCD_MEMORY_CLK/RGMII1_RCTL/UART5_TXD/MCASP1_ACLKX/MMC2_DAT0/MCASP0_ACLKR/GPIO3_4)
MII1_RXERR: R133.1 U5.J15(GMII1_RXERR/RMII1_RXERR/SPI1_D1/I2C1_SCL/MCASP1_FSX/UART5_RTSN/UART2_TXD/GPIO3_2)
MII1_TXCLK: R134.1 U5.K18(GMII1_TXCLK/UART2_RXD/RGMII1_TCLK/MMC0_DAT7/MMC1_DAT0/UART1_DCDN/MCASP0_ACLKX/GPIO3_9)
MII1_TXD0: U5.K17(GMII1_TXD0/RMII1_TXD0/RGMII1_TD0/MCASP1_AXR2/MCASP1_ACLKR/EQEP0B_IN/MMC1_CLK/GPIO0_28) U14.22(TXD0)
MII1_TXD1: U5.K16(GMII1_TXD1/RMII1_TXD1/RGMII1_TD1/MCASP1_FSR/MCASP1_AXR1/EQEP0A_IN/MMC1_CMD/GPIO0_21) U14.23(TXD1)
MII1_TXD2: U5.K15(GMII1_TXD2/DCAN0_RX/RGMII1_TD2/UART4_TXD/MCASP1_AXR0/MMC2_DAT2/MCASP0_AHCLKX/GPIO0_17) U14.24(TXD2)
MII1_TXD3: U5.J18(GMII1_TXD3/DCAN0_TX/RGMII1_TD3/UART4_RXD/MCASP1_FSX/MMC2_DAT1/MCASP0_FSR/GPIO0_16) U14.25(TXD3)
MII1_TXEN: U5.J16(GMII1_TXEN/RMII1_TXEN/RGMII1_TCTL/TIMER4/MCASP1_AXR0/EQEP0_INDEX/MMC2_CMD/GPIO3_3) U14.21(TXEN)
MMC0_CD: P2.19(EMU4) P10.10(CD) R157.1 U5.C15(SPI0_CS1/UART3_RXD/ECAP1_IN_PWM1_OUT/MMC0_POW/XDMA_EVENT_INTR2/MMC0_SDCD/EMU4/GPIO0_6)
MMC0_CLKO: P10.5(CLOCK) R152.2 U5.G17(MMC0_CLK/GPMC_A24/UART3_CTSN/UART2_RXD/DCAN1_TX/PR1_PRU0_PRU_R30_12/PR1_PRU0_PRU_R31_12/GPIO2_30)
MMC0_CMD: P10.3(CMD) R151.2 U5.G18(MMC0_CMD/GPMC_A25/UART3_RTSN/UART2_TXD/DCAN1_RX/PR1_PRU0_PRU_R30_13/PR1_PRU0_PRU_R31_13/GPIO2_31)
MMC0_DAT0: P10.7(DAT0) R153.2 U5.G16(MMC0_DAT0/GPMC_A23/UART5_RTSN/UART3_TXD/UART1_RIN/PR1_PRU0_PRU_R30_11/PR1_PRU0_PRU_R31_11/GPIO2_29)
MMC0_DAT1: P10.8(DAT1) R154.2 U5.G15(MMC0_DAT1/GPMC_A22/UART5_CTSN/UART3_RXD/UART1_DTRN/PR1_PRU0_PRU_R30_10/PR1_PRU0_PRU_R31_10/GPIO2_28)
MMC0_DAT2: P10.1(DAT2) R150.2 U5.F18(MMC0_DAT2/GPMC_A21/UART4_RTSN/TIMER6/UART1_DSRN/PR1_PRU0_PRU_R30_9/PR1_PRU0_PRU_R31_9/GPIO2_27)
MMC0_DAT3: P10.2(CD/DAT3) R155.2 U5.F17(MMC0_DAT3/GPMC_A20/UART4_CTSN/TIMER5/UART1_DCDN/PR1_PRU0_PRU_R30_8/PR1_PRU0_PRU_R31_8/GPIO2_26)
MMC1_CLK: P8.21(11) R110.2 U5.U9(GPMC_CSN1/GPMC_CLK/MMC1_CLK/PRT1EDIO_DATA_IN6/PRT1_EDIO_DATA_OUT6/PR1_PRU1_PRU_R30_12/PR1_PRU1_PRU_R31_12/GPIO1_30) U13.M6(CLK)
MMC1_CMD: P8.20(35) R109.2 U5.V9(GPMC_CSN2/GPMC_BE1N/MMC1_CMD/PR1_EDIO_DATA_IN7/PR1_EDIO_DATA_OUT7/PR1_PRU1_PRU_R30_13/PR1_PRU1_PRU_R31_13/GPIO1_31) U13.M5(CMD)
MMC1_DAT0: P8.25(13) R101.2 U5.U7(GPMC_AD0/MMC1_DAT0//////GPIO1_0) U13.A3(DAT0)
MMC1_DAT1: P8.24(37) R102.2 U5.V7(GPMC_AD1/MMC1_DAT1//////GPIO1_1) U13.A4(DAT1)
MMC1_DAT2: P8.5(3) R103.2 U5.R8(GPMC_AD2/MMC1_DAT2//////GPIO1_2) U13.A5(DAT2)
MMC1_DAT3: P8.6(28) R104.2 U5.T8(GPMC_AD3/MMC1_DAT3//////GPIO1_3) U13.B2(DAT3)
MMC1_DAT4: P8.23(12) R105.2 U5.U8(GPMC_AD4/MMC1_DAT4//////GPIO1_4) U13.B3(DAT4)
MMC1_DAT5: P8.22(36) R106.2 U5.V8(GPMC_AD5/MMC1_DAT5//////GPIO1_5) U13.B4(DAT5)
MMC1_DAT6: P8.3(2) R107.2 U5.R9(GPMC_AD6/MMC1_DAT6//////GPIO1_6) U13.B5(DAT6)
MMC1_DAT7: P8.4(27) R108.2 U5.T9(GPMC_AD7/MMC1_DAT7//////GPIO1_7) U13.B6(DAT7)
MODE2: R113.1 R138.2 U14.15(COL/CRS_DV/MODE2)
OSC1_IN: C21.2 U5.A6(OSC1_IN) Y1.1
OSC1_OUT: C22.2 U5.A4(OSC1_OUT) Y1.4
P_BYPASS: C4.2 U2.47(BYPASS)
P_INT_LDO: C3.2 U2.48(INT_LDO)
P_L1: L1.1 U2.20(L1)
P_L2: L2.1 U2.23(L2)
P_L3: L3.1 U2.31(L3)
PHY_VDDCR: C134.1 C136.1 U14.6(VDDCR)
PHY_XTAL1: C143.1 R141.2 R142.1 Y3.1
PHY_XTAL2: R141.1 R143.1 U14.4(XTAL2)
PHYX: C142.1 R143.2 Y3.2
PMIC_INT: R1.2 U2.45(INT) U5.B18(NNMI)
PMIC_PGOOD: U2.26(PGOOD) U5.B15(PORZn) U16.2(A)
PMIC_POWR_EN: U2.9(PWR_EN) U5.C6(PMIC_POWER_EN)
PROC_A15: R18.1 U5.A15(EVENT_INTR0/TIMER4/CLKOUT1/SPI1_CS1/PR1PRU1R31_16/EMU2/GPIO0_19)
PWR_BUT: P9.9(5) S3.2(B1) S3.4(B2) U2.25(PB_IN)
PWR_LEDR: D1.1(C) R12.2
RBIAS: R144.1 U14.32(RBIAS)
RCLKIN: C161.1 R140.2 R142.2 U14.5(XTAL1/CLKIN)
REFCLKO: C162.2 R118.1 R124.2 R131.2 U14.7(RXCLK/PHYAD1)
RXD0/MODE0: R112.1 R128.2 U14.11(RXD0/MODE0)
RXD1/MODE1: R114.1 R127.2 U14.10(RXD1/MODE1)
RXD2/RMIISEL: R117.1 R126.2 U14.9(RXD2/RMIISEL)
RXD3/PHYAD2: R116.1 R125.2 U14.8(RXD3/PHYAD2)
RXDV: R129.2 U14.26(RXDV)
RXER/PHYAD0: R115.1 R133.2 U14.13(RXER/RXD4/PHYAD0)
RXN: C138.1 P5.2(RD-) R121.1 U14.30(RXN)
RXP: C137.1 P5.1(RD+) R120.1 U14.31(RXP)
SPI1_CS0: P9.28(39) U5.C12(MCASP0_AHCLKR/EHRPWM0_SYNCI_O/MCASP0_AXR2/SPI1_CS0/ECAP2_IN_PWM2_OUT/PR1_PRU0_PRU_R30_3/PR1_PRU0_PRU_R31_3/GPIO3_17)
SPI1_D0: P9.29(15) U5.B13(MCASP0_FSX/EHRPWM0B//SPI1_D0/MMC1_SDCD/PR1_PRU0_PRU_R30_1/PR1_PRU0_PRU_R31_1/GPIO3_15)
SPI1_D1: P9.30(40) U5.D12(MCASP0_AXR0/EHRPWM0_TRIPZONE_INPUT//SPI1_D1/MMC2_SDCD/PR1_PRU0_PRU_R30_2/PR1_PRU0_PRU_R31_2/GPIO3_16)
SPI1_SCLK: P9.31(16) U5.A13(MCASP0_ACLKX/EHRPWM0A//SPI1_SCLK/MMC0_SDCD/PR1_PRU0_PRU_R30_0/PR1_PRU0_PRU_R31_0/GPIO3_14)
SYS_5V: C7.2 C8.2 C10.2 C13.2 C17.1 C34.1 P9.7(4) P9.8(29) R71.1 R72.1 R73.1 R74.1 U2.2(VINLDO) U2.7(SYS1) U2.8(SYS2) U2.21(VIN_DCDC1) U2.22(VIN_DCDC2) U2.32(VIN_DCDC3) U2.39(LDO3_IN) U2.42(LDO4_IN) U4.2(IN) U8.2(IN1) U8.3(IN2)
SYS_RESETn: C24.1 C30.1 P2.15(SRST) P9.10(30) R14.2 S1.2(B1) S1.4(B2) U5.A10(NRESET_INOUT) U14.19(nRST) U16.4(Y)
TCT_RCT: C141.1 P5.4(RCT) P5.5(TCT) R137.1
TESTOUT: TP3.1(TP) U5.A3(TESTOUT)
TIMER4: P8.7(4) U5.R7(GPMC_ADVN_ALE/TIMER4/GPIO2_2)
TIMER5: P8.9(5) U5.T6(GPMC_BE0N_CLE/TIMER5/GPIO2_5)
TIMER6: P8.10(30) U5.U6(GPMC_WEN/TIMER6/GPIO2_4)
TIMER7: P8.8(29) U5.T7(GPMC_OEN_REN/TIMER7/EMU4/GPIO2_3)
TXCLK: R134.2 U14.20(TXCLK)
TXN: C140.1 P5.6(TD-) R123.1 U14.28(TXN)
TXP: C139.1 P5.3(TD+) R122.1 U14.29(TXP)
U5_H18: R28.1 U5.H18(RMII1_REFCLK/XDMA_EVENT_INTR2/SPI1_CS0/UART5_TXD/MCASP1_AXR3/MMC0_POW/MCASP1_AHCLKX/GPIO0_29)
U5_R13: R160.1 U5.R13(GPMC_A0/GMII2_TXEN/RGMII2_TCTL/RMII2_TXEN/GPMC_A16/PR1_MII_MT1_CLK/EHRPWM1_TRIPZONE_INPUT/GPIO1_16)
U5_T13: R161.1 U5.T13(GPMC_CSN3/MMC2_CMD/PR1_MDIO_DATA/GPIO2_0)
UART0_RX: U5.E15(UART0_RXD/SPI1_CS0/DCAN0_TX/I2C2_SDA/ECAP2_IN_PWM2_OUT/PR1_PRU1_PRU_R30_14/PR1_PRU1_PRU_R31_14/GPIO1_10) U15.6(1Y)
UART0_TX: U5.E16(UART0_TXD/SPI1_CS1/DCAN0_RX/I2C2_SCL/ECAP1_IN_PWM1_OUT/PR1_PRU1_PRU_R30_15/PR1_PRU1_PRU_R31_15/GPIO1_11) U15.5(2A)
UART1_RXD: P9.26(38) U5.D16(UART1_RXD/MMC1_SDWP/DCAN1_TX/I2C1_SDA//PR1_UART0_RXD/PR1_PRU1_PRU_R31_16/GPIO0_14)
UART1_TXD: P9.24(37) U5.D15(UART1_TXD/MMC2_SDWP/DCAN1_RX/I2C1_SCL//PR1_UART0_TXD/PR1_PRU0_PRU_R31_16/GPIO0_15)
UART2_RXD: J5.1 P9.22(36) U5.A17(SPI0_SCLK/UART2_RXD/I2C2_SDA/EHRPWM0A/PR1_UART0_CTS_N/PR1_EDIO_SOF/EMU2/GPIO0_2)
UART2_TXD: J5.2 P9.21(11) U5.B17(SPI0_D0/UART2_TXD/I2C2_SCL/EHRPWM0B/PR1_UART0_RTS_N/PR1_EDIO_LATCH_IN/EMU3/GPIO0_3)
UART4_RXD: P9.11(6) U5.T17(GPMC_WAIT0/GM112_CRS/GPMC_CSN4/RMII2_CRS_DV/MMC1_SDCD/PR1_MII1_RXDV/UART4_RXD/GPIO0_30)
UART4_TXD: P9.13(7) U5.U17(GPMC_WPN/GMII2_RXERR/GPMC_CSN5/RMII2_RXERR/MMC2_SDCD/PR1_MDIO_MDCLK/UART4_TXD/GPIO0_31)
USB0_DM: P4.2(D-) U5.N18(USB0_DM) U10.2(D-)
USB0_DP: P4.3(D+) U5.N17(USB0_DP) U10.1(D+)
USB0_ID: P4.4(ID) U5.P16(USB0_ID) U10.3(ID)
USB1_DM: P3.2(P2) U5.R18(USB1_DM) U9.2(D-)
USB1_DP: P3.3(P3) U5.R17(USB1_DP) U9.1(D+)
USB1_DRVVBUS: R53.1 U5.F15(USB1_DRVVBUS/GPIO3_13) U8.4(EN)
USB1_ID: R49.2 U5.P17(USB1_ID)
USB1_OCn: R52.2 U5.T16(GPMC_A10/GMII2_RXD1/RGMII2_RD1/RMII2_RXD1/GPMC_A26/PR1_MII1_CRS/MCASP0_AXR0/GPIO1_26) U8.5(~{OC})
USB1_PWR: C35.1 FB7.1 FB8.2 U8.6(OUT3) U8.7(OUT2) U8.8(OUT1) U9.6(VBUS)
USB1_VBUS: FB8.1 U5.T18(USB1_VBUS)
USB_DC: C1.2 C36.1 P4.1(VB) R159.1 R168.1 U2.12(USB) U10.6(VBUS)
USR0: Q1.2(5) R76.1 U5.V15(GPMC_A5/GMII2_TXD0/RGMII2_TD0/RMII2_TXD0/GPMC_A21/PR1_MII1_RXD3/EQEP1B_IN/GPIO1_21)
USR1: Q1.5 R77.1 U5.U15(GPMC_A6/GMII2_TXCLK/RGMII2_TCLK/MMC2_DAT4/GPMC_A22/PR1_MII1_RXD2/EQEP1_INDEX/GPIO1_22)
USR2: Q2.2(5) R78.1 U5.T15(GPMC_A7/GMII2_RXCLK/RGMII2_RCLK/MMC2_DAT5/GPMC_A23/PR1_MII1_RXD1/EQEP1_STROBE/GPIO1_23)
USR3: Q2.5 R79.1 U5.V16(GPMC_A8/GMII2_RXD3/RGMII2_RD3/MMC2_DAT6/GPMC_A24/PR1_MII1_RXD0/MCASP0_ACLKX/GPIO1_24)
VDCDC1: L1.2 R6.1 U2.19(VDCDC1)
VIO: R7.2 U2.18(VIO) U16.5(VCC)
VLDO1: R5.1 R7.1 R8.1 U2.3(VLDO1)
VREFP_ADC: C31.1 C32.1 C33.1 R27.2 U5.B9(VREFP)
VRTC: C16.1 C105.1 R5.2 R26.1 U5.D7(VDDS_RTC)
WAKEUP: R26.2 U2.13(WAKEUP) U5.C5(EXT_WAKEUP)
WP: R156.2 TP4.1(TP) U7.5(WP)
XDMA_EVENT_INTR0: P2.17(EMU2) R18.2
YEL_C: P5.11(YELC) R130.2
YELA: C164.1 C166.1 P5.12(YELA) R135.1 U14.2(LED2/nINTSEL)
ZQ: R99.2 U12.L8(ZQ)
N21757673: C19.1 R10.1 R11.2 U4.4(ADJ)
N21769115: R75.2 S2.1(A1) S2.3(A2)
N22155575: R159.2 U5.P15(USB0_VBUS)
N22248684: R167.1 Y4.3(CLK)
N22287501: R162.1 U3.4(Y)
N22287555: U3.2(A) U5.R14(GPMC_A4/GMII2_TXD1/RGMII2_TD1/RMII2_TXD1/GPMC_A20/PR1_MII1_TXD0/EQEP1A_IN/GPIO1_20)
N22420400: TP5.1(TP) U2.4(BAT1) U2.5(BAT2)
N22420444: TP6.1(TP) U2.6(BAT_SENSE)
N22420447: TP7.1(TP) U2.11(TS)
N22488252: TP9.1(TP) U5.E17(UART0_RTSN/UART4_TXD/DCAN1_RX/I2C1_SCL/SPI1_D1/SPI1_CS0/PR1_EDC_SYNC1_OUT/GPIO1_9)
N22648410: C25.1 R17.1 U17.1(XIN/CXIN) Y2.2
N22648422: C26.1 R17.2 U17.2(CKOUT) Y2.1
N22649826: R171.2 U17.3(SSON)
N22650321: R172.2 R174.1 U17.6(ADS0)
N22650344: R173.1 R175.2 U17.7(ADS1)
N22650388: U5.V10(OSC0_IN) U17.5(MOD_OUT)

Not connected (* = marked no-connect by the designer): J1 2* 3* 6*; P2 6(NC)*; P5 7(NC)*; U2 14(MUX_IN)* 15(NC)* 16(MUX_OUT)* 17(NC1)* 33(ISINK2)* 34(ISINK1)* 35(ISET1)* 36(ISET2)* 37(L4)* 38(FB_WLED)* 44(RESET)*; U3 1(NC)*; U5 E18(UART0_CTSN/UART4_RXD/DCAN1_TX/I2C1_SDA/SPI1_D0/TIMER7/PR1_EDC_SYNC0_OUT/GPIO1_8)* F16(USB0_DRVVBUS/GPIO0_18) M5(VPP) M15(USB0_CE) P18(USB1_CE) U11(OSC0_OUT); U9 3(ID)* 5(NC)*; U10 5(NC)*; U12 J1(NC1)* J9(NC2)* L1(NC3)* L9(NC4)*; U13 A1(NC11)* A2(NC4)* A6(NC5)* A7(NC6)* A8(NC7)* A9(NC18)* A10(NC95)* A11(NC94)* A12(NC93)* A13(NC92)* A14(NC91)* B1(NC90)* B7(NC89)* B8(NC74)* B9(NC53)* B10(NC52)* B11(NC51)* B12(NC50)* B13(NC49)* B14(NC19)* C1(NC34)* C3(NC33)* C5(NC32)* C7(NC31)* C8(NC30)* C9(NC29)* C10(NC25)* C11(NC23)* C12(NC22)* C13(NC21)* C14(NC20)* D1(NC48)* D2(NC46)* D3(NC39)* D4(NC38)* D12(NC37)* D13(NC36)* D14(NC35)* E1(NC1)* E2(NC2)* E3(NC3)* E5(NC121)* E8(NC8)* E9(NC9)* E10(NC10)* E12(NC12)* E13(NC13)* E14(NC14)* F1(NC15)* F2(NC16)* F3(NC17)* F10(NC24)* F12(NC26)* F13(NC27)* F14(NC28)* G1(NC88)* G2(NC81)* G3(NC79)* G10(NC78)* G12(NC40)* G13(NC41)* G14(NC42)* H1(NC43)* H2(NC44)* H3(NC45)* H5(NC47)* H12(NC54)* H13(NC55)* H14(NC56)* J1(NC57)* J2(NC58)* J3(NC59)* J5(NC60)* J12(NC117)* J13(NC69)* J14(NC70)* K1(NC71)* K2(NC72)* K3(NC73)* K6(NC123)* K7(NC77)* K10(NC80)* K12(NC82)* K13(NC83)* K14(NC84)* L1(NC85)* L2(NC86)* L3(NC87)* L12(NC96)* L13(NC97)* L14(NC98)* M1(NC99)* M2(NC100)* M3(NC101)* M7(NC105)* M8(NC106)* M9(NC107)* M10(NC108)* M11(NC109)* M12(NC110)* M13(NC111)* M14(NC112)* N1(NC113)* N3(NC115)* N6(NC122)* N7(NC118)* N8(NC119)* N9(NC120)* N10(NC75)* N11(NC76)* N12(NC68)* N13(NC67)* N14(NC66)* P1(NC65)* P2(NC64)* P7(NC63)* P8(NC61)* P9(NC62)* P10(NC114)* P11(NC104)* P12(NC103)* P13(NC102)* P14(NC116)*; U16 1(NC)*; Y1 2* 3*

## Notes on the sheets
sheet 1
- REV
- Description
- DATE
- BY
- PAGE NO.
- SCHEMATIC PAGE
- v1
- First release
  PCB version is v1
- 3/6/2015
- QXN
- 1
- COVER PAGE
- 2
- POWER MANAGEMENT
- v1c
- 1.Changed the SRAM to the MT41K256M16TW-107:P.
  2.Changed the eMMC to the MTFC4GACAJCN-1M WT.
  3.Changed the PCB version to v1c
- 3/22/2016
- QXN
- 3
- PROCESSOR 1 OF 3, JTAG HEADER
- 4
- PROCESSOR 2 OF 3, UAB PORTS
- 5
- PROCESSOR 3 OF 3
- 6
- LED, CONFIGURATION AND BUTTON
- 7
- DDR3 MEMORY
- 8
- eMMC FLASH
- 9
- 10/100 ETHERNET
- 10
- EXP CONN, uSD
- This work is licensed under the Creative Commons Attribution 4.0 International License.
  To view a copy of this license,visit
  http://creativecommons.org/licenses/by-sa/4.0
- This schematic is  *NOT SUPPORTED* and DOES NOT constitute
  a reference design. Only Community support is allowed via
  resources at BeagleBoard.org/discuss.
  THERE IS NO WARRANTY FOR THIS DESIGN , TO THE EXTENT
  PERMITTED BY APPLICABLE LAW. EXCEPT WHEN OTHERWISE STATED
  IN WRITING THE COPYRIGHT HOLDERS AND/OR OTHER PARTIES
  PROVIDE THE DESIGN IS WITHOUT WARRANTY OF ANY KIND, EITHER
  EXPRESSED OR IMPLIED, INCLUDING, BUT NOT LIMITED TO, THE
  IMPLIED WARRANTIES OF MERCHANTABILITY AND FITNESS FOR A
  PARTICULAR PURPOSE. THE ENTIRE RISK AS TO THE QUALITY AND
  PERFORMANCE OF THE DESIGN IS WITH YOU. SHOULD THE DESIGN
  PROVE DEFECTIVE, YOU ASSUME THE COST OF ALL NECESSARY
  SERVICING, REPAIR OR CORRECTION.
sheet 2
- Battery access pins.
  Pins are randomly
  placed to fit them in,
  but will be able to tie
  into them either with a
  cape or wires. Pins will
  not be populated.
- select wether the
  usb can provide1A
  current power
- POWER
  BUTTON
- 1.5V
- POWER LED
- 500mA
sheet 3
- SYS_BOOT0
- SYS_BOOT1
- uSD BOOT
- USR0
- USR1
- USR2
- USR3
- SYS_BOOT2
- SYS_BOOT3
- SYS_BOOT4
- SYS_BOOT5
- User LED's
- SYS_BOOT6
- SYS_BOOT7
- SYS_BOOT8
- SYS_BOOT9
- SYS_BOOT10
- SYS_BOOT11
- SYS_BOOT12
- SYS_BOOT13
- SYS_BOOT14
- SYS_BOOT15
- Boot Configuration
sheet 4
- DDR3L SDRAM
- MT41K256M16TW-107:P
- D2516EC4BXGGB
- 4Gb DDR3
sheet 5
- MTFC4GACAAAM-1M WT
- KE4CN2H5A-A58
- MTFC4GACAJCN-1M WT
sheet 6
- CAUTION: USED ON BOARD
- CAUTION: USED ON BOARD
- EXPANSION HEADER
- EXPANSION HEADER
- Board ID
- 256KX8
- uSD CONNECTOR
- GROVE CONNECTOR
sheet 8
- ETHERNET
  CONNECTOR
- ESD_RING
- ACTIVE WHEN LINK PRESENT.
  BLINKS OFF DURING ACTIVITY.
- ACTIVE WHEN AT 100MB
sheet 9
- Mark pin 1
  clearly
- POWERDOWN
  ISOLATION
- UART0 Serial
  Port
- USB to
  TTL Serial
  Cable
  3.3V
- USB PC
  CONNECTOR
- USB HOST
sheet 10
- 3.3V
- RESET
- 1.8V
- 1.8V
- 3.3V
- H
- External clock
  to the McASP0
  interface.
- Oscillator can be disabled
  via SW for power down
  modes or if GPIO3_21
  needs to be used.
